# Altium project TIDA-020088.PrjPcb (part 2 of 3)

## Sheet TIDA-020088_TAS6684_1.SchDoc
size 431 x 279 mm; Date: Not shown in title block; ApprovedBy: Not shown in title block; CheckedBy: Not shown in title block; Author: Not shown in title block; CompanyName: Not shown in title block; Engineer: Not shown in title block; Organization: Not shown in title block; Address1: Not shown in title block; Address2: Not shown in title block; Address3: Not shown in title block; Address4: Not shown in title block; DocumentNumber: 1; Revision: Use project parameter SCH_Rev; SheetNumber: 7; SheetTotal: 8; PageSetup: Record=PageOptions¦CenterHorizontal=True¦CenterVertical=True¦PrintScale=1.00¦XCorrection=1.00¦YCorrection=1.00¦PrintKind=0¦BorderSize=5000000¦LeftOffset=0¦BottomOffset=0¦Orientation=2¦PaperLength=1000¦PaperWidth=1000¦Scale=100¦PaperSource=15¦PrintQuality=600¦MediaType=1¦DitherType=10¦PaperKind=Letter¦PrintScaleMode=1
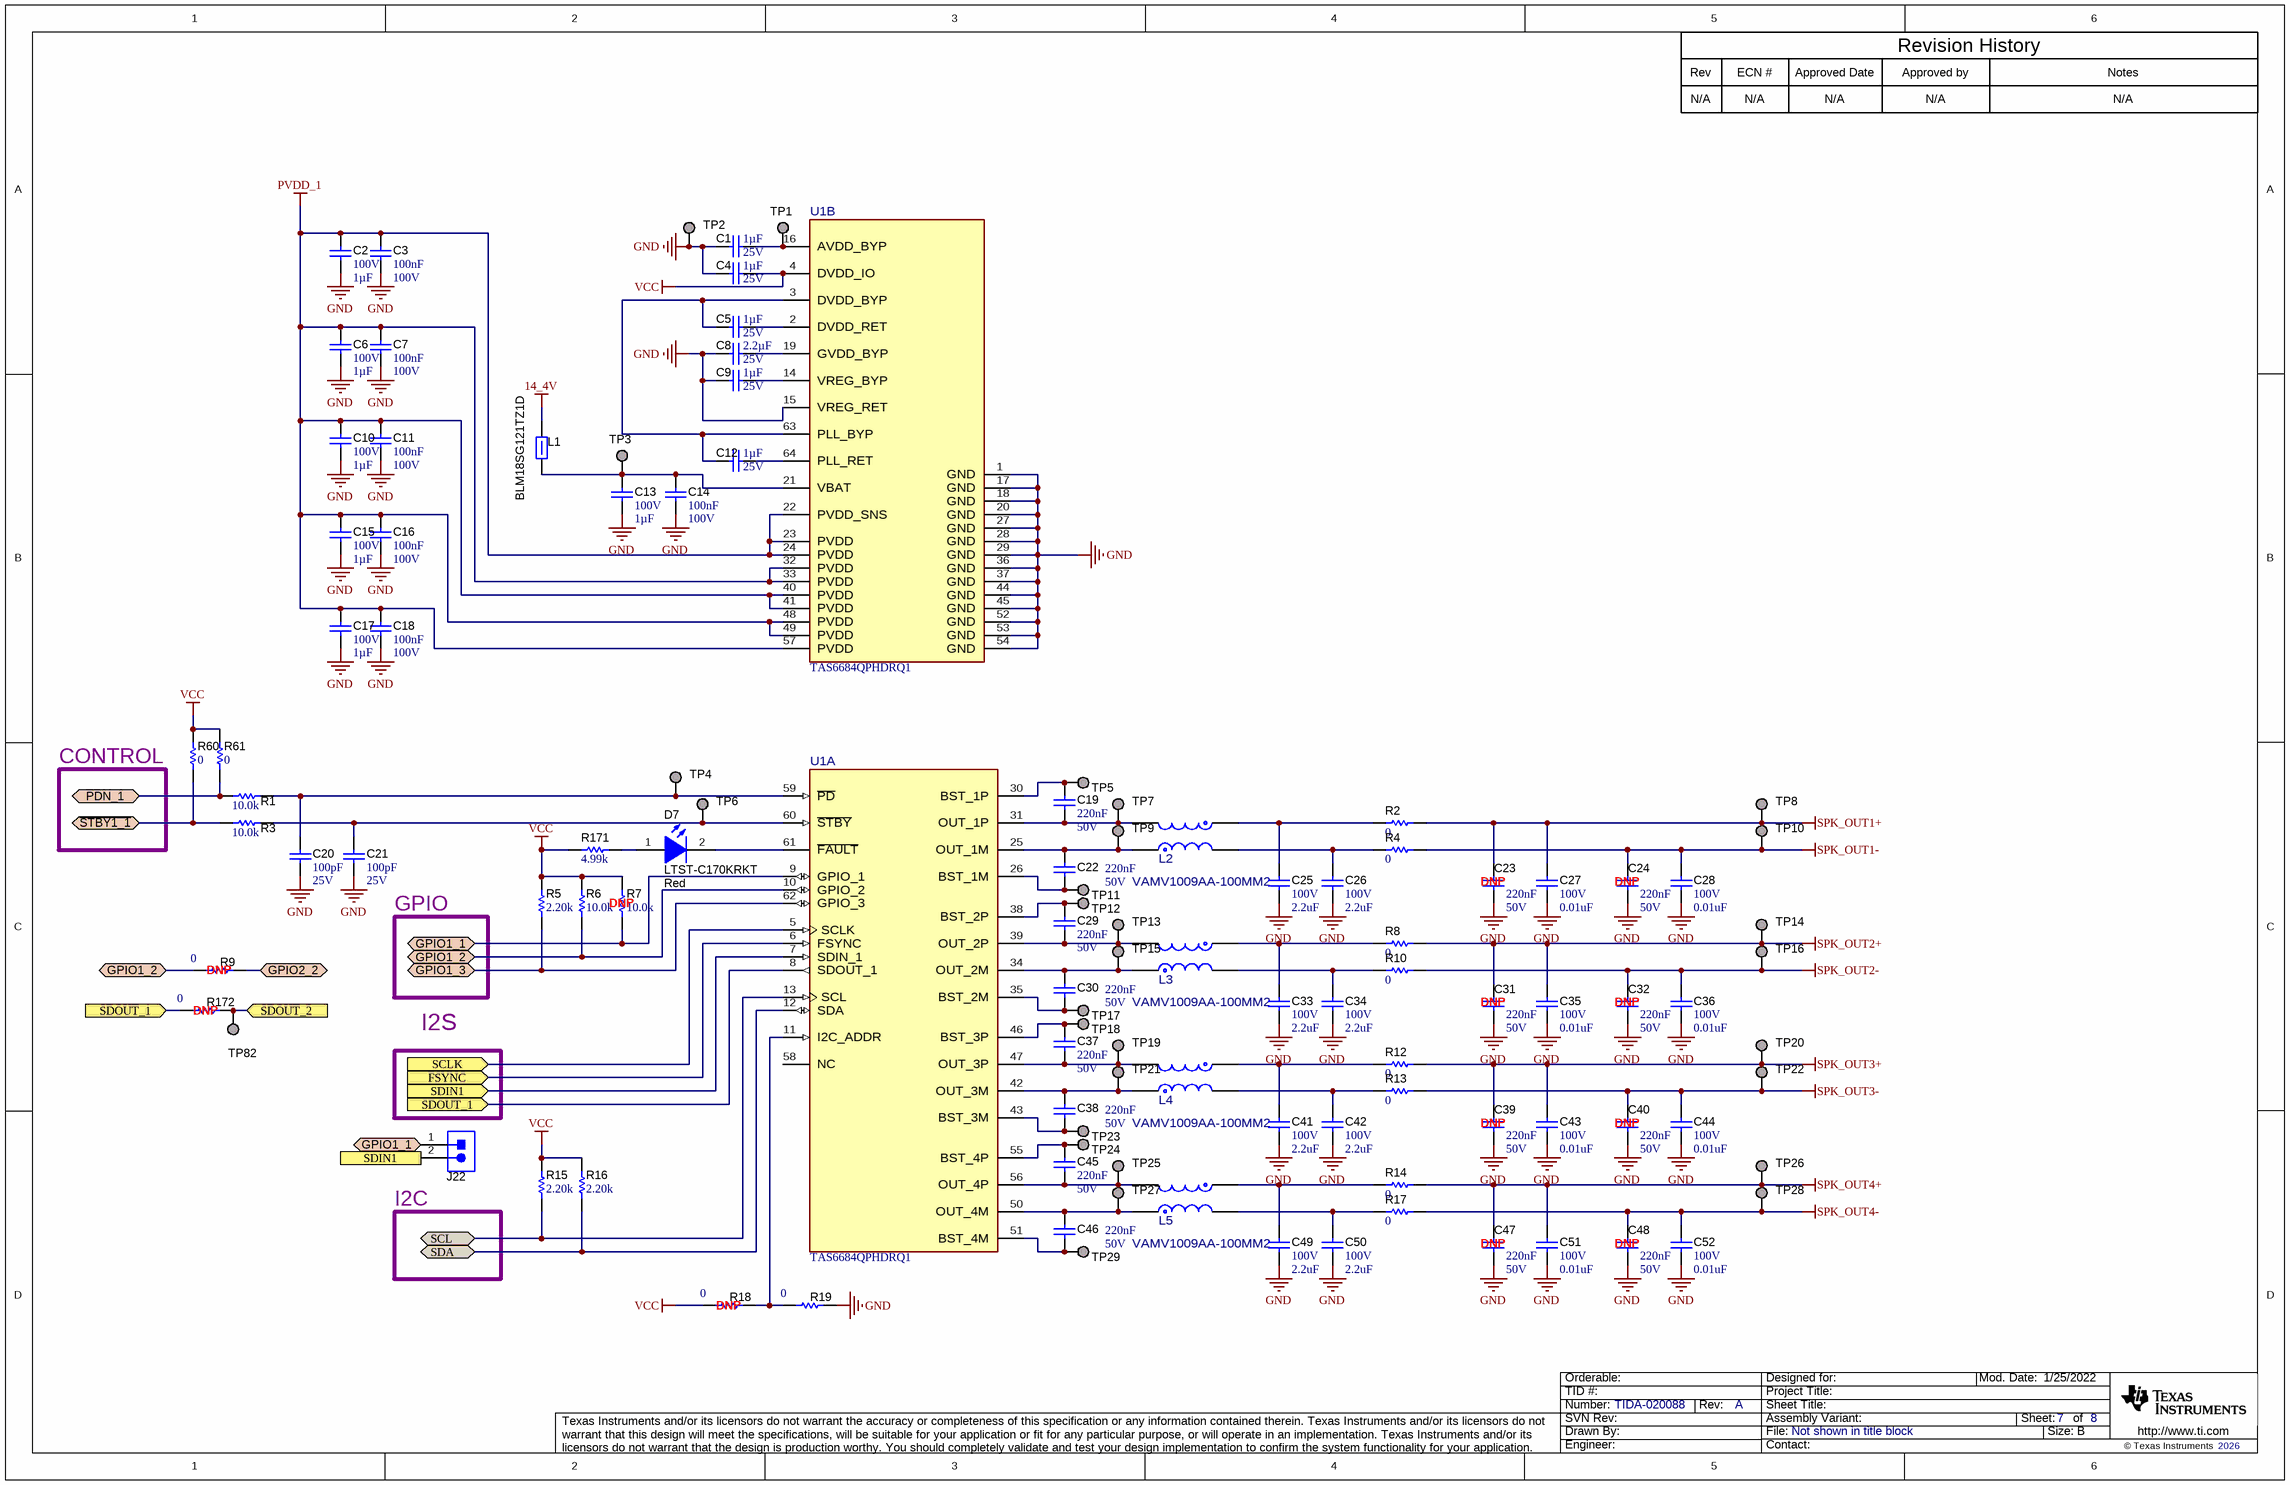
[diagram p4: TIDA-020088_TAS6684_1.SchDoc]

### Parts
C1  Cap_F: 1µF  VDC_V: 25V  [0603]  (hidden comment: GCM188R71E105KA64D)
C2  VDC_V: 100V  ValueDisplayed: 1µF  [1206]  (hidden comment: GCJ31CR72A105KA01K)
C3  Cap_F: 100nF  VDC_V: 100V  [0603]  (hidden comment: GCJ188R72A104KA01D)
C4  Cap_F: 1µF  VDC_V: 25V  [0603]  (hidden comment: GCM188R71E105KA64D)
C5  Cap_F: 1µF  VDC_V: 25V  [0603]  (hidden comment: GCM188R71E105KA64D)
C6  VDC_V: 100V  ValueDisplayed: 1µF  [1206]  (hidden comment: GCJ31CR72A105KA01K)
C7  Cap_F: 100nF  VDC_V: 100V  [0603]  (hidden comment: GCJ188R72A104KA01D)
C8  Cap_F: 2.2µF  VDC_V: 25V  [0805_HV]  (hidden comment: GCM21BR71E225KA73L)
C9  Cap_F: 1µF  VDC_V: 25V  [0603]  (hidden comment: GCM188R71E105KA64D)
C10  VDC_V: 100V  ValueDisplayed: 1µF  [1206]  (hidden comment: GCJ31CR72A105KA01K)
C11  Cap_F: 100nF  VDC_V: 100V  [0603]  (hidden comment: GCJ188R72A104KA01D)
C12  Cap_F: 1µF  VDC_V: 25V  [0603]  (hidden comment: GCM188R71E105KA64D)
C13  VDC_V: 100V  ValueDisplayed: 1µF  [1206]  (hidden comment: GCJ31CR72A105KA01K)
C14  Cap_F: 100nF  VDC_V: 100V  [0603]  (hidden comment: GCJ188R72A104KA01D)
C15  VDC_V: 100V  ValueDisplayed: 1µF  [1206]  (hidden comment: GCJ31CR72A105KA01K)
C16  Cap_F: 100nF  VDC_V: 100V  [0603]  (hidden comment: GCJ188R72A104KA01D)
C17  VDC_V: 100V  ValueDisplayed: 1µF  [1206]  (hidden comment: GCJ31CR72A105KA01K)
C18  Cap_F: 100nF  VDC_V: 100V  [0603]  (hidden comment: GCJ188R72A104KA01D)
C19  Cap_F: 220nF  VDC_V: 50V  [0603]  (hidden comment: GCM188R71H224KA64D)
C20  Cap_F: 100pF  VDC_V: 25V  [0201_033]  (hidden comment: GCM033R71E101KA03D)
C21  Cap_F: 100pF  VDC_V: 25V  [0201_033]  (hidden comment: GCM033R71E101KA03D)
C22  Cap_F: 220nF  VDC_V: 50V  [0603]  (hidden comment: GCM188R71H224KA64D)
C23  DNP  Cap_F: 220nF  VDC_V: 50V  [0603]  (no BOM)
C24  DNP  Cap_F: 220nF  VDC_V: 50V  [0603]  (no BOM)
C25  VDC_V: 100V  ValueDisplayed: 2.2uF  [1210_250]  (hidden comment: CGA6N3X7R2A225K230AB)
C26  VDC_V: 100V  ValueDisplayed: 2.2uF  [1210_250]  (hidden comment: CGA6N3X7R2A225K230AB)
C27  VDC_V: 100V  ValueDisplayed: 0.01uF  [0603]  (hidden comment: CGA3E2X7R2A103K080AA)
C28  VDC_V: 100V  ValueDisplayed: 0.01uF  [0603]  (hidden comment: CGA3E2X7R2A103K080AA)
C29  Cap_F: 220nF  VDC_V: 50V  [0603]  (hidden comment: GCM188R71H224KA64D)
C30  Cap_F: 220nF  VDC_V: 50V  [0603]  (hidden comment: GCM188R71H224KA64D)
C31  DNP  Cap_F: 220nF  VDC_V: 50V  [0603]  (no BOM)
C32  DNP  Cap_F: 220nF  VDC_V: 50V  [0603]  (no BOM)
C33  VDC_V: 100V  ValueDisplayed: 2.2uF  [1210_250]  (hidden comment: CGA6N3X7R2A225K230AB)
C34  VDC_V: 100V  ValueDisplayed: 2.2uF  [1210_250]  (hidden comment: CGA6N3X7R2A225K230AB)
C35  VDC_V: 100V  ValueDisplayed: 0.01uF  [0603]  (hidden comment: CGA3E2X7R2A103K080AA)
C36  VDC_V: 100V  ValueDisplayed: 0.01uF  [0603]  (hidden comment: CGA3E2X7R2A103K080AA)
C37  Cap_F: 220nF  VDC_V: 50V  [0603]  (hidden comment: GCM188R71H224KA64D)
C38  Cap_F: 220nF  VDC_V: 50V  [0603]  (hidden comment: GCM188R71H224KA64D)
C39  DNP  Cap_F: 220nF  VDC_V: 50V  [0603]  (no BOM)
C40  DNP  Cap_F: 220nF  VDC_V: 50V  [0603]  (no BOM)
C41  VDC_V: 100V  ValueDisplayed: 2.2uF  [1210_250]  (hidden comment: CGA6N3X7R2A225K230AB)
C42  VDC_V: 100V  ValueDisplayed: 2.2uF  [1210_250]  (hidden comment: CGA6N3X7R2A225K230AB)
C43  VDC_V: 100V  ValueDisplayed: 0.01uF  [0603]  (hidden comment: CGA3E2X7R2A103K080AA)
C44  VDC_V: 100V  ValueDisplayed: 0.01uF  [0603]  (hidden comment: CGA3E2X7R2A103K080AA)
C45  Cap_F: 220nF  VDC_V: 50V  [0603]  (hidden comment: GCM188R71H224KA64D)
C46  Cap_F: 220nF  VDC_V: 50V  [0603]  (hidden comment: GCM188R71H224KA64D)
C47  DNP  Cap_F: 220nF  VDC_V: 50V  [0603]  (no BOM)
C48  DNP  Cap_F: 220nF  VDC_V: 50V  [0603]  (no BOM)
C49  VDC_V: 100V  ValueDisplayed: 2.2uF  [1210_250]  (hidden comment: CGA6N3X7R2A225K230AB)
C50  VDC_V: 100V  ValueDisplayed: 2.2uF  [1210_250]  (hidden comment: CGA6N3X7R2A225K230AB)
C51  VDC_V: 100V  ValueDisplayed: 0.01uF  [0603]  (hidden comment: CGA3E2X7R2A103K080AA)
C52  VDC_V: 100V  ValueDisplayed: 0.01uF  [0603]  (hidden comment: CGA3E2X7R2A103K080AA)
D7  LTST-C170KRKT  value Red  [LED_LTST-C170_Red]
J22  TSW-102-07-G-S  [TSW-102-07-G-S]  (value not drawn)
L1  BLM18SG121TZ1D  [0603]
L2  VAMV1009AA-100MM2  [FP-VAMV1009AA-100MM2_SMT_CMC_9MM2_10MM2-MFG]
L3  VAMV1009AA-100MM2  [FP-VAMV1009AA-100MM2_SMT_CMC_9MM2_10MM2-MFG]
L4  VAMV1009AA-100MM2  [FP-VAMV1009AA-100MM2_SMT_CMC_9MM2_10MM2-MFG]
L5  VAMV1009AA-100MM2  [FP-VAMV1009AA-100MM2_SMT_CMC_9MM2_10MM2-MFG]
R1  ValueDisplayed: 10.0k  [0402]  (hidden comment: CRCW040210K0FKED)
R2  ValueDisplayed: 0  [1210]  (hidden comment: CRCW12100000Z0EAHP)
R3  ValueDisplayed: 10.0k  [0402]  (hidden comment: CRCW040210K0FKED)
R4  ValueDisplayed: 0  [1210]  (hidden comment: CRCW12100000Z0EAHP)
R5  ValueDisplayed: 2.20k  [0402]  (hidden comment: CRCW04022K20FKED)
R6  ValueDisplayed: 10.0k  [0402]  (hidden comment: CRCW040210K0FKED)
R7  DNP  ValueDisplayed: 10.0k  [0402]  (no BOM)
R8  ValueDisplayed: 0  [1210]  (hidden comment: CRCW12100000Z0EAHP)
R9  DNP  ValueDisplayed: 0  [0603]  (no BOM)
R10  ValueDisplayed: 0  [1210]  (hidden comment: CRCW12100000Z0EAHP)
R12  ValueDisplayed: 0  [1210]  (hidden comment: CRCW12100000Z0EAHP)
R13  ValueDisplayed: 0  [1210]  (hidden comment: CRCW12100000Z0EAHP)
R14  ValueDisplayed: 0  [1210]  (hidden comment: CRCW12100000Z0EAHP)
R15  ValueDisplayed: 2.20k  [0402]  (hidden comment: CRCW04022K20FKED)
R16  ValueDisplayed: 2.20k  [0402]  (hidden comment: CRCW04022K20FKED)
R17  ValueDisplayed: 0  [1210]  (hidden comment: CRCW12100000Z0EAHP)
R18  DNP  ValueDisplayed: 0  [0603]  (no BOM)
R19  ValueDisplayed: 0  [0603]  (hidden comment: CRCW06030000Z0EA)
R60  ValueDisplayed: 0  [0603]  (hidden comment: CRCW06030000Z0EA)
R61  ValueDisplayed: 0  [0603]  (hidden comment: CRCW06030000Z0EA)
R171  ValueDisplayed: 4.99k  [0402]  (hidden comment: CRCW04024K99FKED)
R172  DNP  ValueDisplayed: 0  [0603]  (no BOM)
TP1  TP_SM_1MM  [TP_SM_1MM]  (value not drawn)  (no BOM)
TP2  TP_SM_1MM  [TP_SM_1MM]  (value not drawn)  (no BOM)
TP3  TP_SM_1MM  [TP_SM_1MM]  (value not drawn)  (no BOM)
TP4  TP_SM_1MM  [TP_SM_1MM]  (value not drawn)  (no BOM)
TP5  TP_SM_1MM  [TP_SM_1MM]  (value not drawn)  (no BOM)
TP6  TP_SM_1MM  [TP_SM_1MM]  (value not drawn)  (no BOM)
TP7  TP_SM_1MM  [TP_SM_1MM]  (value not drawn)  (no BOM)
TP8  TP_SM_1MM  [TP_SM_1MM]  (value not drawn)  (no BOM)
TP9  TP_SM_1MM  [TP_SM_1MM]  (value not drawn)  (no BOM)
TP10  TP_SM_1MM  [TP_SM_1MM]  (value not drawn)  (no BOM)
TP11  TP_SM_1MM  [TP_SM_1MM]  (value not drawn)  (no BOM)
TP12  TP_SM_1MM  [TP_SM_1MM]  (value not drawn)  (no BOM)
TP13  TP_SM_1MM  [TP_SM_1MM]  (value not drawn)  (no BOM)
TP14  TP_SM_1MM  [TP_SM_1MM]  (value not drawn)  (no BOM)
TP15  TP_SM_1MM  [TP_SM_1MM]  (value not drawn)  (no BOM)
TP16  TP_SM_1MM  [TP_SM_1MM]  (value not drawn)  (no BOM)
TP17  TP_SM_1MM  [TP_SM_1MM]  (value not drawn)  (no BOM)
TP18  TP_SM_1MM  [TP_SM_1MM]  (value not drawn)  (no BOM)
TP19  TP_SM_1MM  [TP_SM_1MM]  (value not drawn)  (no BOM)
TP20  TP_SM_1MM  [TP_SM_1MM]  (value not drawn)  (no BOM)
TP21  TP_SM_1MM  [TP_SM_1MM]  (value not drawn)  (no BOM)
TP22  TP_SM_1MM  [TP_SM_1MM]  (value not drawn)  (no BOM)
TP23  TP_SM_1MM  [TP_SM_1MM]  (value not drawn)  (no BOM)
TP24  TP_SM_1MM  [TP_SM_1MM]  (value not drawn)  (no BOM)
TP25  TP_SM_1MM  [TP_SM_1MM]  (value not drawn)  (no BOM)
TP26  TP_SM_1MM  [TP_SM_1MM]  (value not drawn)  (no BOM)
TP27  TP_SM_1MM  [TP_SM_1MM]  (value not drawn)  (no BOM)
TP28  TP_SM_1MM  [TP_SM_1MM]  (value not drawn)  (no BOM)
TP29  TP_SM_1MM  [TP_SM_1MM]  (value not drawn)  (no BOM)
TP82  TP_SM_1MM  [TP_SM_1MM]  (value not drawn)  (no BOM)
U1  TAS6684QPHDRQ1  [PHD0064B-MFG]  (parts A,B of 2)

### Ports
FSYNC (in), GPIO1_1 (bidir), GPIO1_2 (bidir), GPIO1_3 (bidir), GPIO2_2 (bidir), PDN_1 (bidir), SCL (bidir), SCLK (in), SDA (bidir), SDIN1 (in), SDOUT_1 (in), SDOUT_2 (in), ~{STBY1_1} (bidir)

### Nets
14_4V: L1.1  [project net BIAS]
GND: C1.1 C2.2 C3.1 C4.1 C6.2 C7.2 C8.2 C9.1 C10.2 C11.2 C13.2 C14.2 C15.2 C16.2 C17.2 C18.2 C20.2 C21.2 C23.2 C24.2 C25.2 C26.2 C27.2 C28.2 C31.2 C32.2 C33.2 C34.2 C35.2 C36.2 C39.2 C40.2 C41.2 C42.2 C43.2 C44.2 C47.2 C48.2 C49.2 C50.2 C51.2 C52.2 R19.2 TP2.1 U1.1(GND) U1.15(VREG_RET) U1.17(GND) U1.18(GND) U1.20(GND) U1.27(GND) U1.28(GND) U1.29(GND) U1.36(GND) U1.37(GND) U1.44(GND) U1.45(GND) U1.52(GND) U1.53(GND) U1.54(GND)
PVDD_1: C2.1 C3.2 C6.1 C7.1 C10.1 C11.1 C15.1 C16.1 C17.1 C18.1 U1.22(PVDD_SNS) U1.23(PVDD) U1.24(PVDD) U1.32(PVDD) U1.33(PVDD) U1.40(PVDD) U1.41(PVDD) U1.48(PVDD) U1.49(PVDD) U1.57(PVDD)
SPK_OUT1+: C23.1 C27.1 R2.2 TP8.1
SPK_OUT1-: C24.1 C28.1 R4.2 TP10.1
SPK_OUT2+: C31.1 C35.1 R8.2 TP14.1
SPK_OUT2-: C32.1 C36.1 R10.2 TP16.1
SPK_OUT3+: C39.1 C43.1 R12.2 TP20.1
SPK_OUT3-: C40.1 C44.1 R13.2 TP22.1
SPK_OUT4+: C47.1 C51.1 R14.2 TP26.1
SPK_OUT4-: C48.1 C52.1 R17.2 TP28.1
VCC: C4.2 R5.2 R6.2 R7.2 R15.2 R16.2 R18.1 R60.2 R61.2 R171.1 U1.4(DVDD_IO)
NetC1_2: C1.2 TP1.1 U1.16(AVDD_BYP)
NetC5_1: C5.1 C12.1 U1.3(DVDD_BYP) U1.63(PLL_BYP)
NetC5_2: C5.2 U1.2(DVDD_RET)
NetC8_1: C8.1 U1.19(GVDD_BYP)
NetC9_2: C9.2 U1.14(VREG_BYP)
NetC12_2: C12.2 U1.64(PLL_RET)
NetC13_1: C13.1 C14.1 L1.2 TP3.1 U1.21(VBAT)
NetC19_1: C19.1 TP5.1 U1.30(BST_1P)
NetC19_2: C19.2 L2.4(2_Finish) TP7.1 U1.31(OUT_1P)
NetC20_1: C20.1 R1.1 TP4.1 U1.59(~{PD})
NetC21_1: C21.1 R3.2 TP6.1 U1.60(~{STBY})
NetC22_1: C22.1 L2.1(1_Start) TP9.1 U1.25(OUT_1M)
NetC22_2: C22.2 TP11.1 U1.26(BST_1M)
NetC25_1: C25.1 L2.3(2_Start) R2.1
NetC26_1: C26.1 L2.2(1_Finish) R4.1
NetC29_1: C29.1 TP12.1 U1.38(BST_2P)
NetC29_2: C29.2 L3.4(2_Finish) TP13.1 U1.39(OUT_2P)
NetC30_1: C30.1 L3.1(1_Start) TP15.1 U1.34(OUT_2M)
NetC30_2: C30.2 TP17.1 U1.35(BST_2M)
NetC33_1: C33.1 L3.3(2_Start) R8.1
NetC34_1: C34.1 L3.2(1_Finish) R10.1
NetC37_1: C37.1 TP18.1 U1.46(BST_3P)
NetC37_2: C37.2 L4.4(2_Finish) TP19.1 U1.47(OUT_3P)
NetC38_1: C38.1 L4.1(1_Start) TP21.1 U1.42(OUT_3M)
NetC38_2: C38.2 TP23.1 U1.43(BST_3M)
NetC41_1: C41.1 L4.3(2_Start) R12.1
NetC42_1: C42.1 L4.2(1_Finish) R13.1
NetC45_1: C45.1 TP24.1 U1.55(BST_4P)
NetC45_2: C45.2 L5.4(2_Finish) TP25.1 U1.56(OUT_4P)
NetC46_1: C46.1 L5.1(1_Start) TP27.1 U1.50(OUT_4M)
NetC46_2: C46.2 TP29.1 U1.51(BST_4M)
NetC49_1: C49.1 L5.3(2_Start) R14.1
NetC50_1: C50.1 L5.2(1_Finish) R17.1
NetD7_1: D7.1(A) R171.2
NetD7_2: D7.2(K) U1.61(~{FAULT})
NetJ2_2: U1.5(SCLK) ; port SCLK
NetJ4_2: U1.6(FSYNC) ; port FSYNC
NetJ6_2: J22.2 U1.7(SDIN_1) ; port SDIN1
NetJ11_2: R15.1 U1.13(SCL) ; port SCL
NetJ11_3: R16.1 U1.12(SDA) ; port SDA
NetJ22_1: J22.1 R7.1 U1.9(GPIO_1) ; port GPIO1_1
NetR1_2: R1.2 R61.1 ; port PDN_1
NetR3_1: R3.1 R60.1 ; port ~{STBY1_1}
NetR5_1: R5.1 U1.62(GPIO_3) ; port GPIO1_3
NetR6_1: R6.1 R9.1 U1.10(GPIO_2) ; port GPIO1_2
NetR9_2: R9.2 ; port GPIO2_2
NetR18_2: R18.2 R19.1 U1.11(I2C_ADDR)
NetR142_2: R172.1 U1.8(SDOUT_1) ; port SDOUT_1
NetR143_2: R172.2 TP82.1 ; port SDOUT_2

Not connected (* = marked no-connect by the designer): U1 58(NC)

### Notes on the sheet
- Rev
- N/A
- ECN #
- Approved Date
- Approved by
- Revision History
- Notes
- CONTROL
- (near C21) GPIO
- I2S
- (near J22) I2C

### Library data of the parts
C1 C4 C5 C9 C12 = CMP-0007139-3: CAP, CERM, 1 uF, 25 V, +/- 10%, X7R, AEC-Q200 Grade 1, 0603; Manufacturer: MuRata; TaMin_C: -55°C; Polarized: N; SizeAreaWB_mm2: 4.68; Value1: Unknown; U/M: EA; Value: 1uF; TaMax_C: 125°C; SizeZ_mm: 1; SizeX_mm: 1.6; SizeY_mm: 0.8; SizeArea_mm2: 1.28; AEC Qualified: Y; AEC Category: Q200
C2 C6 C10 C13 C15 C17 = CMP-0750040-1: CAP, CERM, 1 µF, 100 V,+/- 10%, X7R, AEC-Q200 Grade 1, 1206; Manufacturer: MuRata; Value: 1uF; U/M: EA; SizeX_mm: 3.2; Polarized: N; TaMin_C: -55°C; SizeZ_mm: 1.35; SizeY_mm: 1.6; AEC Category: Q200; SizeArea_mm2: 5.12; TaMax_C: 125°C; AEC Grade: 1; AEC Qualified: Y; SizeAreaWB_mm2: 10.92
C3 C7 C11 C14 C16 C18 = CMP-0064935-2: CAP, CERM, 0.1 uF, 100 V,+/- 10%, X7R, AEC-Q200 Grade 1, 0603; Manufacturer: MuRata; TaMin_C: -55°C; Polarized: N; SizeAreaWB_mm2: 4.68; Value1: Unknown; U/M: EA; Value: 0.1uF; TaMax_C: 125°C; SizeZ_mm: 1; SizeX_mm: 1.6; SizeY_mm: 0.8; SizeArea_mm2: 1.28; AEC Qualified: Y; AEC Category: Q200
C8 = CMP-0083622-1: CAP, CERM, 2.2 µF, 25 V,+/- 10%, X7R, AEC-Q200 Grade 1, 0805; Manufacturer: MuRata; TaMin_C: -55°C; Polarized: N; SizeAreaWB_mm2: 6.75; U/M: EA; Value: 2.2uF; TaMax_C: 125°C; SizeZ_mm: 1.45; SizeX_mm: 2; SizeY_mm: 1.25; Cap_Case: 0805; SizeArea_mm2: 2.5; AEC Qualified: Y; AEC Grade: 1; AEC Category: Q200
C19 C22 C29 C30 C37 C38 C45 C46 = CMP-0007145-4: CAP, CERM, 0.22 uF, 50 V, +/- 10%, X7R, AEC-Q200 Grade 1, 0603; Manufacturer: MuRata; TaMin_C: -55°C; Polarized: N; SizeAreaWB_mm2: 4.68; Value1: Unknown; U/M: EA; Value: 0.22uF; TaMax_C: 125°C; SizeZ_mm: 1; SizeX_mm: 1.6; SizeY_mm: 0.8; SizeArea_mm2: 1.28; AEC Qualified: Y; AEC Category: Q200
C20 C21 = CMP-0009660-3: CAP, CERM, 100 pF, 25 V, +/- 10%, X7R, AEC-Q200 Grade 1, 0201; Manufacturer: MuRata; TaMin_C: -55°C; Polarized: N; SizeAreaWB_mm2: 2.08; U/M: EA; Value: 100pF; TaMax_C: 125°C; SizeZ_mm: 0.33; SizeX_mm: 0.6; SizeY_mm: 0.3; Cap_Case: 0201; SizeArea_mm2: 0.18; AEC Qualified: Y; AEC Grade: 1; AEC Category: Q200; Value1: Unknown
C23 C24 C31 C32 C39 C40 C47 C48 = CMP-0007145-4: CAP, CERM, 0.22 uF, 50 V, +/- 10%, X7R, AEC-Q200 Grade 1, 0603; Manufacturer: MuRata; PartNumber: GCM188R71H224KA64D; TaMin_C: -55°C; Polarized: N; SizeAreaWB_mm2: 4.68; Value1: Unknown; U/M: EA; Value: 0.22uF; TaMax_C: 125°C; SizeZ_mm: 1; SizeX_mm: 1.6; SizeY_mm: 0.8; SizeArea_mm2: 1.28; AEC Qualified: Y; AEC Category: Q200
C25 C26 C33 C34 C41 C42 C49 C50 = CMP-0009152-2: CAP, CERM, 2.2 uF, 100 V, +/- 10%, X7R, AEC-Q200 Grade 1,; Manufacturer: TDK; TaMin_C: -55°C; ESR_ohm: 1.73m; Polarized: N; SizeAreaWB_mm2: 14.7; Value1: 0.00173 ohm; U/M: EA; Value: 2.2uF; TaMax_C: 125°C; SizeZ_mm: 2.5; SizeX_mm: 3.2; SizeArea_mm2: 8; AEC Qualified: Y; Cap_F: 2.2µF; IRMS_A: 5.5932A; AEC Grade: 1; AEC Category: Q200
C27 C28 C35 C36 C43 C44 C51 C52 = CMP-0007082-4: CAP, CERM, 0.01 uF, 100 V, +/- 10%, X7R, AEC-Q200 Grade 1, 0603; Manufacturer: TDK; Value: 0.01uF; SizeZ_mm: 1; AEC Qualified: Y; Cap_F: 10nF; TaMin_C: -55°C; ESR_ohm: 0.2354; Polarized: N; SizeAreaWB_mm2: 4.68; Value1: 0.235428 ohm; U/M: EA; TaMax_C: 125°C; SizeX_mm: 1.6; SizeY_mm: 0.8; SizeArea_mm2: 1.28; IRMS_A: 396.995mA; AEC Category: Q200
D7 = CMP-0002829-3: LED, Red, SMD; Manufacturer: Lite-On; SizeZ_mm: 1.2; Value1: W; SizeY_mm: 1.25; Value2: 2V; SizeArea_mm2: 2.5; SizeX_mm: 2; SizeAreaWB_mm2: 6.75; Io_A: 20mA; Type: AlInGaP
J22 = CMP-0075405-2: Header, 100mil, 2x1, Gold, TH; Manufacturer: Samtec; Pitch_mm: 2.54; Cert_VDE: N; Gender: Male; Cert_CSA: Y; Voltage_V: 550V; Green_REACh: Passed; Current_A: 6.3A; Green_Lifecycle: Active; Row_Count: 1
L1 = CMP-0084877-1: Inductor, Ferrite Bead, Ferrite, 3 A, 120 ohm, AEC-Q200 Grade 1, SMD; Manufacturer: MuRata; SizeAreaWB_mm2: 4.68; DCR_ohm: 120; Value1: 120 ohm; Imax_A: 3A; SizeZ_mm: 1; SizeX_mm: 1.6; SizeY_mm: 0.8; SizeArea_mm2: 1.28; AEC Qualified: Y; AEC Category: Q200
L2-L5 = CMP-0093075-1: Power Choke Coil, 10uH 20% 100kHz, 22mΩ DCR max, Idc 5.8A, Isat 10A; Manufacturer: Cyntec; SizeZ_mm: 11.05mm; AEC Grade: Grade 1; DCR_ohm: 22m; Ind_H: 10µH; AEC Qualified: Yes; Material: Metal Dust
R1 R3 R6 = CMP-0025958-3: RES, 10.0 k, 1%, 0.063 W, AEC-Q200 Grade 0, 0402; Manufacturer: Vishay-Dale; Power_W: 63mW; TempCo: 100 ppm/C; Value_Code: 10k0; Value: 10.0k; EIA_Code: E96; Res_ohm: 10k; SizeX_mm: 1; SizeY_mm: 0.5; SizeZ_mm: 0.6; Value2: 0.063W; AEC Qualified: Y; VDC_V: 50V; AEC Category: Q200; AEC Grade: 0
R2 R4 R8 R10 R12-R14 R17 = CMP-0015017-3: RES, 0, 1%, 0.75 W, AEC-Q200 Grade 0, 1210; Manufacturer: Vishay-Dale; Power_W: 750mW; TempCo: ppm/C; SizeAreaWB_mm2: 14.7; Value: 0; SizeX_mm: 3.2; SizeY_mm: 2.5; SizeZ_mm: 1.35; Value2: 0.75W; SizeArea_mm2: 8; AEC Qualified: Y; AEC Category: Q200
R5 R15 R16 = CMP-0026231-2: RES, 2.20 k, 1%, 0.063 W, AEC-Q200 Grade 0, 0402; Manufacturer: Vishay-Dale; Power_W: 63mW; TempCo: 100 ppm/C; Value_Code: 2k20; Value: 2.20k; Res_ohm: 2.2k; SizeX_mm: 1; SizeY_mm: 0.5; SizeZ_mm: 0.6; Value2: 0.063W; AEC Qualified: Y; AEC Category: Q200; AEC Grade: 0
R7 = CMP-0025958-3: RES, 10.0 k, 1%, 0.063 W, AEC-Q200 Grade 0, 0402; Manufacturer: Vishay-Dale; PartNumber: CRCW040210K0FKED; Power_W: 63mW; TempCo: 100 ppm/C; Value_Code: 10k0; Value: 10.0k; EIA_Code: E96; Res_ohm: 10k; SizeX_mm: 1; SizeY_mm: 0.5; SizeZ_mm: 0.6; Value2: 0.063W; AEC Qualified: Y; VDC_V: 50V; AEC Category: Q200; AEC Grade: 0
R9 R18 R172 = CMP-0025697-4: RES, 0, 5%, 0.1 W, AEC-Q200 Grade 0, 0603; Manufacturer: Vishay-Dale; PartNumber: CRCW06030000Z0EA; AEC Qualified: Y; Power_W: 100mW; SizeZ_mm: 1; VDC_V: 75V; Value: 0; TempCo: 200 ppm/C; Value_Code: 0000; EIA_Code: E24; SizeX_mm: 1.6; SizeY_mm: 0.8; Value2: 0.1W; SizeArea_mm2: 1.28; AEC Category: Q200
R19 = CMP-0025697-4: RES, 0, 5%, 0.1 W, AEC-Q200 Grade 0, 0603; Manufacturer: Vishay-Dale; AEC Qualified: Y; Power_W: 100mW; SizeZ_mm: 1; VDC_V: 75V; Value: 0; TempCo: 200 ppm/C; Value_Code: 0000; EIA_Code: E24; SizeX_mm: 1.6; SizeY_mm: 0.8; Value2: 0.1W; SizeArea_mm2: 1.28; AEC Category: Q200
R60 R61 = CMP-0025697-4: RES, 0, 5%, 0.1 W, AEC-Q200 Grade 0, 0603; Manufacturer: Vishay-Dale; Power_W: 100mW; TempCo: 200 ppm/C; Value_Code: 0000; Value: 0; EIA_Code: E24; SizeX_mm: 1.6; SizeY_mm: 0.8; SizeZ_mm: 1; Value2: 0.1W; SizeArea_mm2: 1.28; AEC Qualified: Y; VDC_V: 75V; AEC Category: Q200
R171 = CMP-0026414-2: RES, 4.99 k, 1%, 0.063 W, AEC-Q200 Grade 0, 0402; Manufacturer: Vishay-Dale; Power_W: 63mW; TempCo: 100 ppm/C; Value_Code: 4k99; Value: 4.99k; EIA_Code: E96; SizeX_mm: 1; SizeY_mm: 0.5; SizeZ_mm: 0.6; Value2: 0.063W; AEC Qualified: Y; VDC_V: 50V; AEC Category: Q200; AEC Grade: 0
TP1-TP29 TP82 = CMP-0003825-1: 1mm Test Point, SMT; Manufacturer: Any
U1 = CMP-0122557-1: 45-V, 13-A Digital Input 4-Channel Automotive Class-D Audio Amplifier with Current Sense and Real-time Load Diagnostics; Manufacturer: Texas Instruments; SizeZ_mm: 1.2mm; AEC Qualified: Yes; AEC Grade: Grade 1; Max Supply Voltage: 45V; Min Supply Voltage: 4.5V; Number Of Channels: 4; Output Current Per Channel: 13A; Power At Speaker R: 215W @ 4Ω; Standoff Height: 0.05mm; TaMax_C: +125°C; TaMin_C: -40°C; TJmax_C: +175°C

## Sheet TIDA-020088_TAS6684_2.SchDoc
size 431 x 279 mm; Date: Not shown in title block; ApprovedBy: Not shown in title block; CheckedBy: Not shown in title block; Author: Not shown in title block; CompanyName: Not shown in title block; Engineer: Not shown in title block; Organization: Not shown in title block; Address1: Not shown in title block; Address2: Not shown in title block; Address3: Not shown in title block; Address4: Not shown in title block; DocumentNumber: 2; Revision: Use project parameter SCH_Rev; SheetNumber: 3; SheetTotal: 8; PageSetup: Record=PageOptions¦CenterHorizontal=True¦CenterVertical=True¦PrintScale=1.00¦XCorrection=1.00¦YCorrection=1.00¦PrintKind=0¦BorderSize=5000000¦LeftOffset=0¦BottomOffset=0¦Orientation=2¦PaperLength=1000¦PaperWidth=1000¦Scale=100¦PaperSource=15¦PrintQuality=600¦MediaType=1¦DitherType=10¦PaperKind=Letter¦PrintScaleMode=1
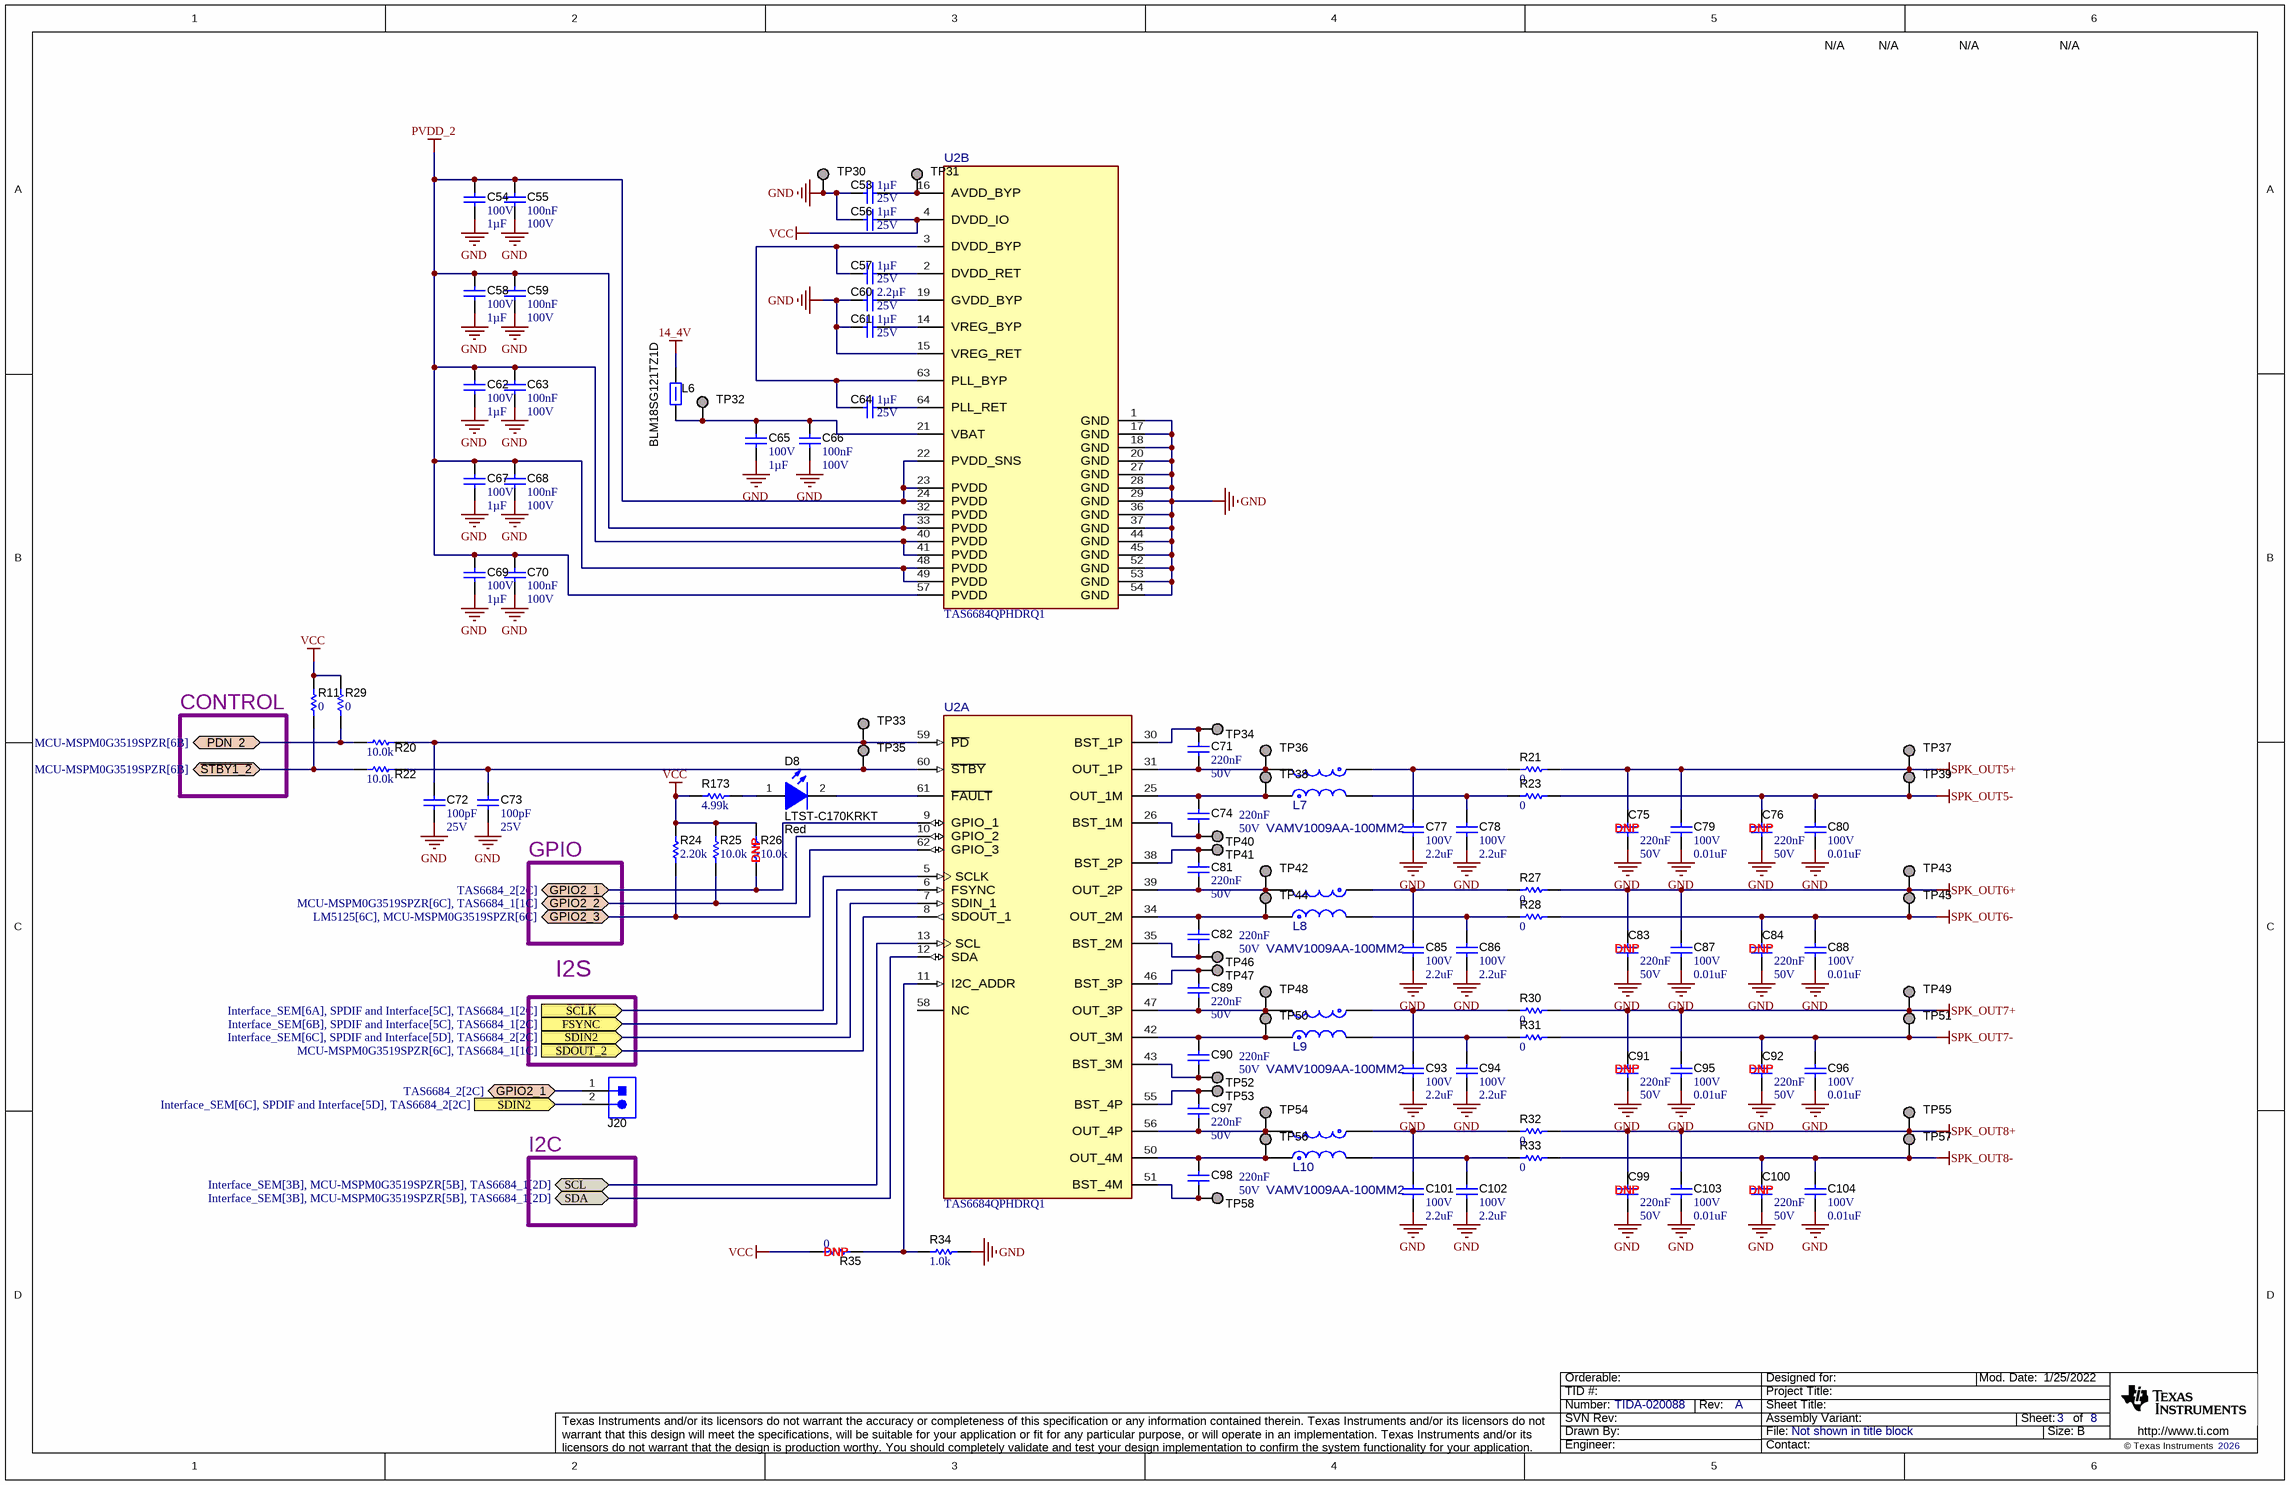
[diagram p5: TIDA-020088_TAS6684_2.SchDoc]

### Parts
C53  Cap_F: 1µF  VDC_V: 25V  [0603]  (hidden comment: GCM188R71E105KA64D)
C54  VDC_V: 100V  ValueDisplayed: 1µF  [1206]  (hidden comment: GCJ31CR72A105KA01K)
C55  Cap_F: 100nF  VDC_V: 100V  [0603]  (hidden comment: GCJ188R72A104KA01D)
C56  Cap_F: 1µF  VDC_V: 25V  [0603]  (hidden comment: GCM188R71E105KA64D)
C57  Cap_F: 1µF  VDC_V: 25V  [0603]  (hidden comment: GCM188R71E105KA64D)
C58  VDC_V: 100V  ValueDisplayed: 1µF  [1206]  (hidden comment: GCJ31CR72A105KA01K)
C59  Cap_F: 100nF  VDC_V: 100V  [0603]  (hidden comment: GCJ188R72A104KA01D)
C60  Cap_F: 2.2µF  VDC_V: 25V  [0805_HV]  (hidden comment: GCM21BR71E225KA73L)
C61  Cap_F: 1µF  VDC_V: 25V  [0603]  (hidden comment: GCM188R71E105KA64D)
C62  VDC_V: 100V  ValueDisplayed: 1µF  [1206]  (hidden comment: GCJ31CR72A105KA01K)
C63  Cap_F: 100nF  VDC_V: 100V  [0603]  (hidden comment: GCJ188R72A104KA01D)
C64  Cap_F: 1µF  VDC_V: 25V  [0603]  (hidden comment: GCM188R71E105KA64D)
C65  VDC_V: 100V  ValueDisplayed: 1µF  [1206]  (hidden comment: GCJ31CR72A105KA01K)
C66  Cap_F: 100nF  VDC_V: 100V  [0603]  (hidden comment: GCJ188R72A104KA01D)
C67  VDC_V: 100V  ValueDisplayed: 1µF  [1206]  (hidden comment: GCJ31CR72A105KA01K)
C68  Cap_F: 100nF  VDC_V: 100V  [0603]  (hidden comment: GCJ188R72A104KA01D)
C69  VDC_V: 100V  ValueDisplayed: 1µF  [1206]  (hidden comment: GCJ31CR72A105KA01K)
C70  Cap_F: 100nF  VDC_V: 100V  [0603]  (hidden comment: GCJ188R72A104KA01D)
C71  Cap_F: 220nF  VDC_V: 50V  [0603]  (hidden comment: GCM188R71H224KA64D)
C72  Cap_F: 100pF  VDC_V: 25V  [0201_033]  (hidden comment: GCM033R71E101KA03D)
C73  Cap_F: 100pF  VDC_V: 25V  [0201_033]  (hidden comment: GCM033R71E101KA03D)
C74  Cap_F: 220nF  VDC_V: 50V  [0603]  (hidden comment: GCM188R71H224KA64D)
C75  DNP  Cap_F: 220nF  VDC_V: 50V  [0603]  (no BOM)
C76  DNP  Cap_F: 220nF  VDC_V: 50V  [0603]  (no BOM)
C77  VDC_V: 100V  ValueDisplayed: 2.2uF  [1210_250]  (hidden comment: CGA6N3X7R2A225K230AB)
C78  VDC_V: 100V  ValueDisplayed: 2.2uF  [1210_250]  (hidden comment: CGA6N3X7R2A225K230AB)
C79  VDC_V: 100V  ValueDisplayed: 0.01uF  [0603]  (hidden comment: CGA3E2X7R2A103K080AA)
C80  VDC_V: 100V  ValueDisplayed: 0.01uF  [0603]  (hidden comment: CGA3E2X7R2A103K080AA)
C81  Cap_F: 220nF  VDC_V: 50V  [0603]  (hidden comment: GCM188R71H224KA64D)
C82  Cap_F: 220nF  VDC_V: 50V  [0603]  (hidden comment: GCM188R71H224KA64D)
C83  DNP  Cap_F: 220nF  VDC_V: 50V  [0603]  (no BOM)
C84  DNP  Cap_F: 220nF  VDC_V: 50V  [0603]  (no BOM)
C85  VDC_V: 100V  ValueDisplayed: 2.2uF  [1210_250]  (hidden comment: CGA6N3X7R2A225K230AB)
C86  VDC_V: 100V  ValueDisplayed: 2.2uF  [1210_250]  (hidden comment: CGA6N3X7R2A225K230AB)
C87  VDC_V: 100V  ValueDisplayed: 0.01uF  [0603]  (hidden comment: CGA3E2X7R2A103K080AA)
C88  VDC_V: 100V  ValueDisplayed: 0.01uF  [0603]  (hidden comment: CGA3E2X7R2A103K080AA)
C89  Cap_F: 220nF  VDC_V: 50V  [0603]  (hidden comment: GCM188R71H224KA64D)
C90  Cap_F: 220nF  VDC_V: 50V  [0603]  (hidden comment: GCM188R71H224KA64D)
C91  DNP  Cap_F: 220nF  VDC_V: 50V  [0603]  (no BOM)
C92  DNP  Cap_F: 220nF  VDC_V: 50V  [0603]  (no BOM)
C93  VDC_V: 100V  ValueDisplayed: 2.2uF  [1210_250]  (hidden comment: CGA6N3X7R2A225K230AB)
C94  VDC_V: 100V  ValueDisplayed: 2.2uF  [1210_250]  (hidden comment: CGA6N3X7R2A225K230AB)
C95  VDC_V: 100V  ValueDisplayed: 0.01uF  [0603]  (hidden comment: CGA3E2X7R2A103K080AA)
C96  VDC_V: 100V  ValueDisplayed: 0.01uF  [0603]  (hidden comment: CGA3E2X7R2A103K080AA)
C97  Cap_F: 220nF  VDC_V: 50V  [0603]  (hidden comment: GCM188R71H224KA64D)
C98  Cap_F: 220nF  VDC_V: 50V  [0603]  (hidden comment: GCM188R71H224KA64D)
C99  DNP  Cap_F: 220nF  VDC_V: 50V  [0603]  (no BOM)
C100  DNP  Cap_F: 220nF  VDC_V: 50V  [0603]  (no BOM)
C101  VDC_V: 100V  ValueDisplayed: 2.2uF  [1210_250]  (hidden comment: CGA6N3X7R2A225K230AB)
C102  VDC_V: 100V  ValueDisplayed: 2.2uF  [1210_250]  (hidden comment: CGA6N3X7R2A225K230AB)
C103  VDC_V: 100V  ValueDisplayed: 0.01uF  [0603]  (hidden comment: CGA3E2X7R2A103K080AA)
C104  VDC_V: 100V  ValueDisplayed: 0.01uF  [0603]  (hidden comment: CGA3E2X7R2A103K080AA)
D8  LTST-C170KRKT  value Red  [LED_LTST-C170_Red]
J20  TSW-102-07-G-S  [TSW-102-07-G-S]  (value not drawn)
L6  BLM18SG121TZ1D  [0603]
L7  VAMV1009AA-100MM2  [FP-VAMV1009AA-100MM2_SMT_CMC_9MM2_10MM2-MFG]
L8  VAMV1009AA-100MM2  [FP-VAMV1009AA-100MM2_SMT_CMC_9MM2_10MM2-MFG]
L9  VAMV1009AA-100MM2  [FP-VAMV1009AA-100MM2_SMT_CMC_9MM2_10MM2-MFG]
L10  VAMV1009AA-100MM2  [FP-VAMV1009AA-100MM2_SMT_CMC_9MM2_10MM2-MFG]
R11  ValueDisplayed: 0  [0603]  (hidden comment: CRCW06030000Z0EA)
R20  ValueDisplayed: 10.0k  [0402]  (hidden comment: CRCW040210K0FKED)
R21  ValueDisplayed: 0  [1210]  (hidden comment: CRCW12100000Z0EAHP)
R22  ValueDisplayed: 10.0k  [0402]  (hidden comment: CRCW040210K0FKED)
R23  ValueDisplayed: 0  [1210]  (hidden comment: CRCW12100000Z0EAHP)
R24  ValueDisplayed: 2.20k  [0402]  (hidden comment: CRCW04022K20FKED)
R25  ValueDisplayed: 10.0k  [0402]  (hidden comment: CRCW040210K0FKED)
R26  DNP  ValueDisplayed: 10.0k  [0402]  (no BOM)
R27  ValueDisplayed: 0  [1210]  (hidden comment: CRCW12100000Z0EAHP)
R28  ValueDisplayed: 0  [1210]  (hidden comment: CRCW12100000Z0EAHP)
R29  ValueDisplayed: 0  [0603]  (hidden comment: CRCW06030000Z0EA)
R30  ValueDisplayed: 0  [1210]  (hidden comment: CRCW12100000Z0EAHP)
R31  ValueDisplayed: 0  [1210]  (hidden comment: CRCW12100000Z0EAHP)
R32  ValueDisplayed: 0  [1210]  (hidden comment: CRCW12100000Z0EAHP)
R33  ValueDisplayed: 0  [1210]  (hidden comment: CRCW12100000Z0EAHP)
R34  ValueDisplayed: 1.0k  [0402]  (hidden comment: CRCW04021K00JNED)
R35  DNP  ValueDisplayed: 0  [0603]  (no BOM)
R173  ValueDisplayed: 4.99k  [0402]  (hidden comment: CRCW04024K99FKED)
TP30  TP_SM_1MM  [TP_SM_1MM]  (value not drawn)  (no BOM)
TP31  TP_SM_1MM  [TP_SM_1MM]  (value not drawn)  (no BOM)
TP32  TP_SM_1MM  [TP_SM_1MM]  (value not drawn)  (no BOM)
TP33  TP_SM_1MM  [TP_SM_1MM]  (value not drawn)  (no BOM)
TP34  TP_SM_1MM  [TP_SM_1MM]  (value not drawn)  (no BOM)
TP35  TP_SM_1MM  [TP_SM_1MM]  (value not drawn)  (no BOM)
TP36  TP_SM_1MM  [TP_SM_1MM]  (value not drawn)  (no BOM)
TP37  TP_SM_1MM  [TP_SM_1MM]  (value not drawn)  (no BOM)
TP38  TP_SM_1MM  [TP_SM_1MM]  (value not drawn)  (no BOM)
TP39  TP_SM_1MM  [TP_SM_1MM]  (value not drawn)  (no BOM)
TP40  TP_SM_1MM  [TP_SM_1MM]  (value not drawn)  (no BOM)
TP41  TP_SM_1MM  [TP_SM_1MM]  (value not drawn)  (no BOM)
TP42  TP_SM_1MM  [TP_SM_1MM]  (value not drawn)  (no BOM)
TP43  TP_SM_1MM  [TP_SM_1MM]  (value not drawn)  (no BOM)
TP44  TP_SM_1MM  [TP_SM_1MM]  (value not drawn)  (no BOM)
TP45  TP_SM_1MM  [TP_SM_1MM]  (value not drawn)  (no BOM)
TP46  TP_SM_1MM  [TP_SM_1MM]  (value not drawn)  (no BOM)
TP47  TP_SM_1MM  [TP_SM_1MM]  (value not drawn)  (no BOM)
TP48  TP_SM_1MM  [TP_SM_1MM]  (value not drawn)  (no BOM)
TP49  TP_SM_1MM  [TP_SM_1MM]  (value not drawn)  (no BOM)
TP50  TP_SM_1MM  [TP_SM_1MM]  (value not drawn)  (no BOM)
TP51  TP_SM_1MM  [TP_SM_1MM]  (value not drawn)  (no BOM)
TP52  TP_SM_1MM  [TP_SM_1MM]  (value not drawn)  (no BOM)
TP53  TP_SM_1MM  [TP_SM_1MM]  (value not drawn)  (no BOM)
TP54  TP_SM_1MM  [TP_SM_1MM]  (value not drawn)  (no BOM)
TP55  TP_SM_1MM  [TP_SM_1MM]  (value not drawn)  (no BOM)
TP56  TP_SM_1MM  [TP_SM_1MM]  (value not drawn)  (no BOM)
TP57  TP_SM_1MM  [TP_SM_1MM]  (value not drawn)  (no BOM)
TP58  TP_SM_1MM  [TP_SM_1MM]  (value not drawn)  (no BOM)
U2  TAS6684QPHDRQ1  [PHD0064B-MFG]  (parts A,B of 2)

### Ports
FSYNC (in, see Interface_SEM[6B], SPDIF and Interface[5C], TAS6684_1[2C]), GPIO2_1 (bidir, see TAS6684_2[2C]), GPIO2_2 (bidir, see MCU-MSPM0G3519SPZR[6C], TAS6684_1[1C]), GPIO2_3 (bidir, see LM5125[6C], MCU-MSPM0G3519SPZR[6C]), PDN_2 (bidir, see MCU-MSPM0G3519SPZR[6B]), SCL (bidir, see Interface_SEM[3B], MCU-MSPM0G3519SPZR[5B], TAS6684_1[2D]), SCLK (in, see Interface_SEM[6A], SPDIF and Interface[5C], TAS6684_1[2C]), SDA (bidir, see Interface_SEM[3B], MCU-MSPM0G3519SPZR[5B], TAS6684_1[2D]), SDIN2 (in, see Interface_SEM[6C], SPDIF and Interface[5D], TAS6684_2[2C]), SDOUT_2 (in, see MCU-MSPM0G3519SPZR[6C], TAS6684_1[1C]), ~{STBY1_2} (bidir, see MCU-MSPM0G3519SPZR[6B])

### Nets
14_4V: L6.1  [project net BIAS]
GND: C53.1 C54.2 C55.1 C56.1 C58.2 C59.2 C60.2 C61.1 C62.2 C63.2 C65.2 C66.2 C67.2 C68.2 C69.2 C70.2 C72.2 C73.2 C75.2 C76.2 C77.2 C78.2 C79.2 C80.2 C83.2 C84.2 C85.2 C86.2 C87.2 C88.2 C91.2 C92.2 C93.2 C94.2 C95.2 C96.2 C99.2 C100.2 C101.2 C102.2 C103.2 C104.2 R34.2 TP30.1 U2.1(GND) U2.15(VREG_RET) U2.17(GND) U2.18(GND) U2.20(GND) U2.27(GND) U2.28(GND) U2.29(GND) U2.36(GND) U2.37(GND) U2.44(GND) U2.45(GND) U2.52(GND) U2.53(GND) U2.54(GND)
PVDD_2: C54.1 C55.2 C58.1 C59.1 C62.1 C63.1 C67.1 C68.1 C69.1 C70.1 U2.22(PVDD_SNS) U2.23(PVDD) U2.24(PVDD) U2.32(PVDD) U2.33(PVDD) U2.40(PVDD) U2.41(PVDD) U2.48(PVDD) U2.49(PVDD) U2.57(PVDD)
SPK_OUT5+: C75.1 C79.1 R21.2 TP37.1
SPK_OUT5-: C76.1 C80.1 R23.2 TP39.1
SPK_OUT6+: C83.1 C87.1 R27.2 TP43.1
SPK_OUT6-: C84.1 C88.1 R28.2 TP45.1
SPK_OUT7+: C91.1 C95.1 R30.2 TP49.1
SPK_OUT7-: C92.1 C96.1 R31.2 TP51.1
SPK_OUT8+: C99.1 C103.1 R32.2 TP55.1
SPK_OUT8-: C100.1 C104.1 R33.2 TP57.1
VCC: C56.2 R11.2 R24.2 R25.2 R26.2 R29.2 R35.1 R173.1 U2.4(DVDD_IO)
NetC53_2: C53.2 TP31.1 U2.16(AVDD_BYP)
NetC57_1: C57.1 C64.1 U2.3(DVDD_BYP) U2.63(PLL_BYP)
NetC57_2: C57.2 U2.2(DVDD_RET)
NetC60_1: C60.1 U2.19(GVDD_BYP)
NetC61_2: C61.2 U2.14(VREG_BYP)
NetC64_2: C64.2 U2.64(PLL_RET)
NetC65_1: C65.1 C66.1 L6.2 TP32.1 U2.21(VBAT)
NetC71_1: C71.1 TP34.1 U2.30(BST_1P)
NetC71_2: C71.2 L7.4(2_Finish) TP36.1 U2.31(OUT_1P)
NetC72_1: C72.1 R20.1 TP33.1 U2.59(~{PD})
NetC73_1: C73.1 R22.2 TP35.1 U2.60(~{STBY})
NetC74_1: C74.1 L7.1(1_Start) TP38.1 U2.25(OUT_1M)
NetC74_2: C74.2 TP40.1 U2.26(BST_1M)
NetC77_1: C77.1 L7.3(2_Start) R21.1
NetC78_1: C78.1 L7.2(1_Finish) R23.1
NetC81_1: C81.1 TP41.1 U2.38(BST_2P)
NetC81_2: C81.2 L8.4(2_Finish) TP42.1 U2.39(OUT_2P)
NetC82_1: C82.1 L8.1(1_Start) TP44.1 U2.34(OUT_2M)
NetC82_2: C82.2 TP46.1 U2.35(BST_2M)
NetC85_1: C85.1 L8.3(2_Start) R27.1
NetC86_1: C86.1 L8.2(1_Finish) R28.1
NetC89_1: C89.1 TP47.1 U2.46(BST_3P)
NetC89_2: C89.2 L9.4(2_Finish) TP48.1 U2.47(OUT_3P)
NetC90_1: C90.1 L9.1(1_Start) TP50.1 U2.42(OUT_3M)
NetC90_2: C90.2 TP52.1 U2.43(BST_3M)
NetC93_1: C93.1 L9.3(2_Start) R30.1
NetC94_1: C94.1 L9.2(1_Finish) R31.1
NetC97_1: C97.1 TP53.1 U2.55(BST_4P)
NetC97_2: C97.2 L10.4(2_Finish) TP54.1 U2.56(OUT_4P)
NetC98_1: C98.1 L10.1(1_Start) TP56.1 U2.50(OUT_4M)
NetC98_2: C98.2 TP58.1 U2.51(BST_4M)
NetC101_1: C101.1 L10.3(2_Start) R32.1
NetC102_1: C102.1 L10.2(1_Finish) R33.1
NetD8_1: D8.1(A) R173.2
NetD8_2: D8.2(K) U2.61(~{FAULT})
NetJ2_2: U2.5(SCLK) ; port SCLK
NetJ4_2: U2.6(FSYNC) ; port FSYNC
NetJ11_2: U2.13(SCL) ; port SCL
NetJ11_3: U2.12(SDA) ; port SDA
NetJ19_2: J20.2 U2.7(SDIN_1) ; port SDIN2
NetJ20_1: J20.1 R26.1 U2.9(GPIO_1) ; port GPIO2_1
NetR9_2: R25.1 U2.10(GPIO_2) ; port GPIO2_2
NetR11_1: R11.1 R22.1 ; port ~{STBY1_2}
NetR20_2: R20.2 R29.1 ; port PDN_2
NetR24_1: R24.1 U2.62(GPIO_3) ; port GPIO2_3
NetR34_1: R34.1 R35.2 U2.11(I2C_ADDR)
NetR143_2: U2.8(SDOUT_1) ; port SDOUT_2

Not connected (* = marked no-connect by the designer): U2 58(NC)

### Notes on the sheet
- N/A
- CONTROL
- (near C73) GPIO
- I2S
- I2C

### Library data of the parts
C53 C56 C57 C61 C64 = CMP-0007139-3: as C1 on sheet TIDA-020088_TAS6684_1
C54 C58 C62 C65 C67 C69 = CMP-0750040-1: as C2 on sheet TIDA-020088_TAS6684_1
C55 C59 C63 C66 C68 C70 = CMP-0064935-2: as C3 on sheet TIDA-020088_TAS6684_1
C60 = CMP-0083622-1: as C8 on sheet TIDA-020088_TAS6684_1
C71 C74 C81 C82 C89 C90 C97 C98 = CMP-0007145-4: as C19 on sheet TIDA-020088_TAS6684_1
C72 C73 = CMP-0009660-3: as C20 on sheet TIDA-020088_TAS6684_1
C75 C76 C83 C84 C91 C92 C99 C100 = CMP-0007145-4: as C23 on sheet TIDA-020088_TAS6684_1
C77 C78 C85 C86 C93 C94 C101 C102 = CMP-0009152-2: as C25 on sheet TIDA-020088_TAS6684_1
C79 C80 C87 C88 C95 C96 C103 C104 = CMP-0007082-4: as C27 on sheet TIDA-020088_TAS6684_1
D8 = CMP-0002829-3: as D7 on sheet TIDA-020088_TAS6684_1
J20 = CMP-0075405-2: as J22 on sheet TIDA-020088_TAS6684_1
L6 = CMP-0084877-1: as L1 on sheet TIDA-020088_TAS6684_1
L7-L10 = CMP-0093075-1: as L2 on sheet TIDA-020088_TAS6684_1
R11 R29 = CMP-0025697-4: as R60 on sheet TIDA-020088_TAS6684_1
R20 R22 R25 = CMP-0025958-3: as R1 on sheet TIDA-020088_TAS6684_1
R21 R23 R27 R28 R30-R33 = CMP-0015017-3: as R2 on sheet TIDA-020088_TAS6684_1
R24 = CMP-0026231-2: as R5 on sheet TIDA-020088_TAS6684_1
R26 = CMP-0025958-3: as R7 on sheet TIDA-020088_TAS6684_1
R34 = CMP-0026852-3: RES, 1.0 k, 5%, 0.063 W, AEC-Q200 Grade 0, 0402; Manufacturer: Vishay-Dale; Power_W: 63mW; TempCo: 200 ppm/C; Value_Code: 1k00; Value: 1.0k; EIA_Code: E24; Res_ohm: 1k; SizeX_mm: 1; SizeY_mm: 0.5; SizeZ_mm: 0.6; Value2: 0.063W; AEC Qualified: Y; VDC_V: 50V; AEC Category: Q200; AEC Grade: 0
R35 = CMP-0025697-4: as R9 on sheet TIDA-020088_TAS6684_1
R173 = CMP-0026414-2: as R171 on sheet TIDA-020088_TAS6684_1
TP30-TP58 = CMP-0003825-1: 1mm Test Point, SMT; Manufacturer: Any
U2 = CMP-0122557-1: as U1 on sheet TIDA-020088_TAS6684_1

## Sheet TIDA-020088_MCU-MSPM0G3519SPZR.SchDoc
size 431 x 279 mm; Date: Not shown in title block; ApprovedBy: Not shown in title block; CheckedBy: Not shown in title block; Author: Not shown in title block; CompanyName: Not shown in title block; Engineer: Not shown in title block; Organization: Not shown in title block; Address1: Not shown in title block; Address2: Not shown in title block; Address3: Not shown in title block; Address4: Not shown in title block; DocumentNumber: 2; Revision: Use project parameter SCH_Rev; SheetNumber: 6; SheetTotal: 8; PageSetup: Record=PageOptions¦CenterHorizontal=True¦CenterVertical=True¦PrintScale=1.00¦XCorrection=1.00¦YCorrection=1.00¦PrintKind=0¦BorderSize=5000000¦LeftOffset=0¦BottomOffset=0¦Orientation=2¦PaperLength=1000¦PaperWidth=1000¦Scale=100¦PaperSource=15¦PrintQuality=600¦MediaType=1¦DitherType=10¦PaperKind=Letter¦PrintScaleMode=1
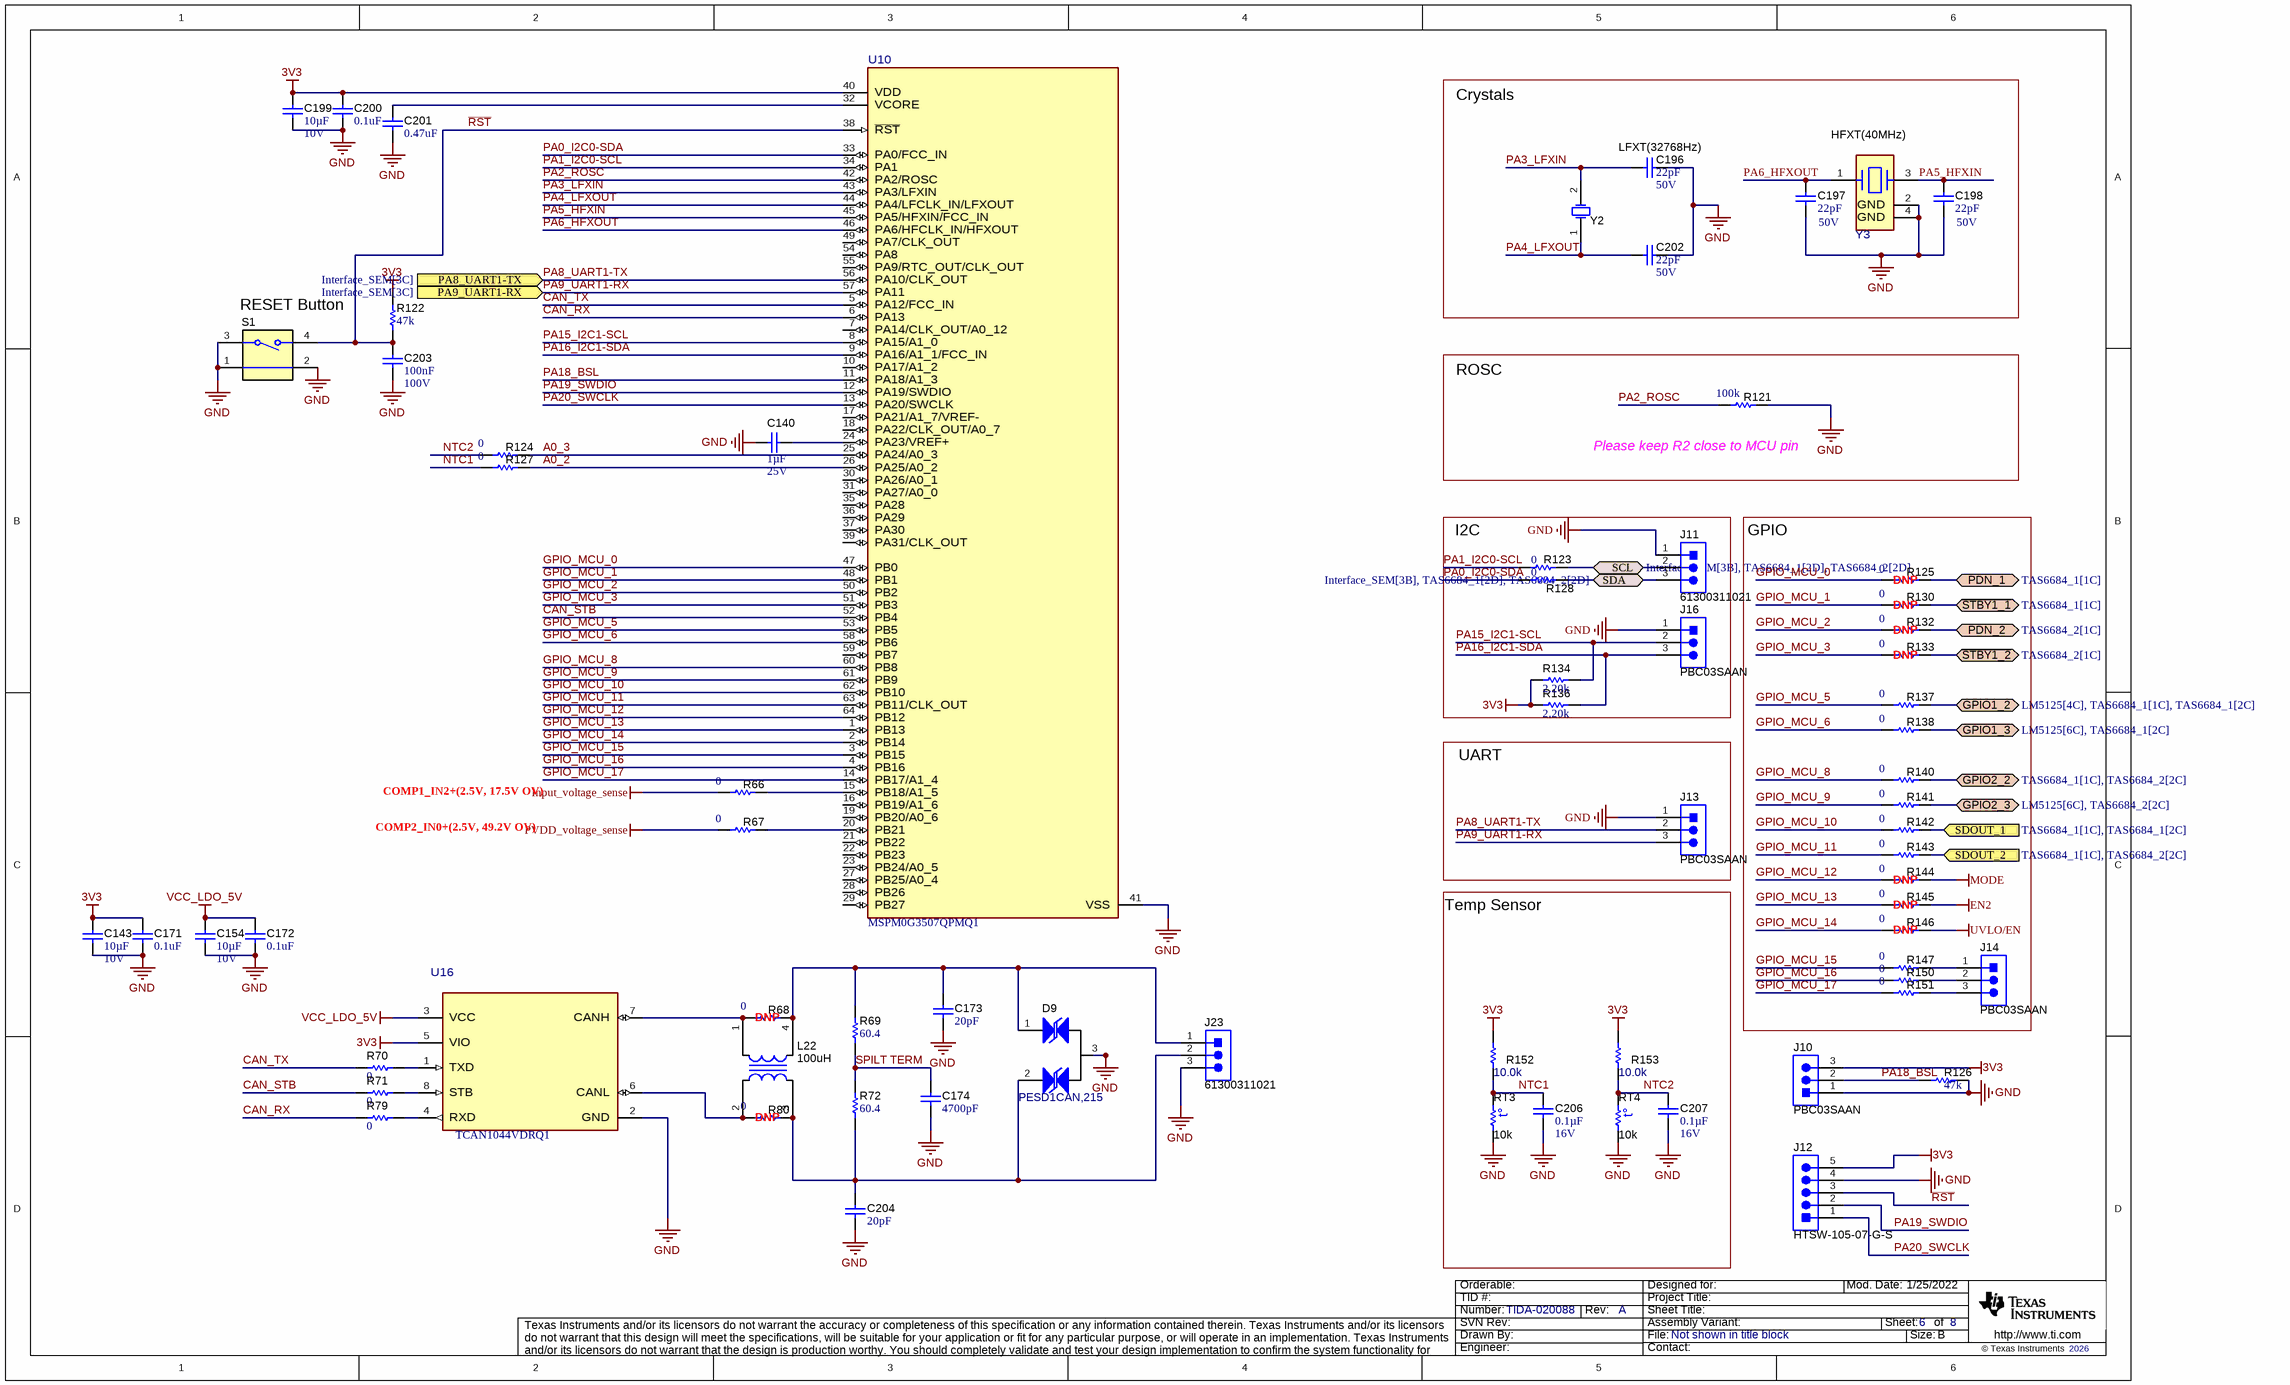
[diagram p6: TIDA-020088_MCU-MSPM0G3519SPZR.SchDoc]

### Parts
C140  Cap_F: 1µF  VDC_V: 25V  [0603]  (hidden comment: GCM188R71E105KA64D)
C143  Cap_F: 10µF  VDC_V: 10V  [0805_HV]  (hidden comment: C0805C106J8RACAUTO)
C154  Cap_F: 10µF  VDC_V: 10V  [0805_HV]  (hidden comment: C0805C106J8RACAUTO)
C171  ValueDisplayed: 0.1uF  [0402]  (hidden comment: GCM155R71H104KE02D)
C172  ValueDisplayed: 0.1uF  [0402]  (hidden comment: GCM155R71H104KE02D)
C173  ValueDisplayed: 20pF  [0402]  (hidden comment: GCQ1555C1H200JB01D)
C174  ValueDisplayed: 4700pF  [0603]  (hidden comment: GCM188R71H472KA37D)
C196  ValueDisplayed: 22pF  VDC_V: 50V  [0402]  (hidden comment: GCM1555C1H220JA16D)
C197  ValueDisplayed: 22pF  VDC_V: 50V  [0402]  (hidden comment: GCM1555C1H220JA16D)
C198  ValueDisplayed: 22pF  VDC_V: 50V  [0402]  (hidden comment: GCM1555C1H220JA16D)
C199  Cap_F: 10µF  VDC_V: 10V  [0805_HV]  (hidden comment: C0805C106J8RACAUTO)
C200  ValueDisplayed: 0.1uF  [0402]  (hidden comment: GCM155R71H104KE02D)
C201  ValueDisplayed: 0.47uF  [0603]  (hidden comment: GCM188R71E474KA64D)
C202  ValueDisplayed: 22pF  VDC_V: 50V  [0402]  (hidden comment: GCM1555C1H220JA16D)
C203  Cap_F: 100nF  VDC_V: 100V  [0603]  (hidden comment: GCJ188R72A104KA01D)
C204  ValueDisplayed: 20pF  [0402]  (hidden comment: GCQ1555C1H200JB01D)
C206  ValueDisplayed: 0.1µF  VDC_V: 16V  [0402]  (hidden comment: GCM155R71C104JA55D)
C207  ValueDisplayed: 0.1µF  VDC_V: 16V  [0402]  (hidden comment: GCM155R71C104JA55D)
D9  PESD1CAN,215  [SOT-23]
J10  PBC03SAAN  [PBC03SAAN]
J11  61300311021  [Wurth_61300311021]
J12  HTSW-105-07-G-S  [Samtec_HTSW-105-07-G-S]
J13  PBC03SAAN  [PBC03SAAN]
J14  PBC03SAAN  [PBC03SAAN]
J16  PBC03SAAN  [PBC03SAAN]
J23  61300311021  [Wurth_61300311021]
L22  ValueDisplayed: 100uH  [ACT45B]  (hidden comment: ACT45B-101-2P-TL003)
R66  ValueDisplayed: 0  [0603]  (hidden comment: CRCW06030000Z0EA)
R67  ValueDisplayed: 0  [0603]  (hidden comment: CRCW06030000Z0EA)
R68  DNP  ValueDisplayed: 0  [0603]  (no BOM)
R69  ValueDisplayed: 60.4  [1206]  (hidden comment: ERJ-8ENF60R4V)
R70  ValueDisplayed: 0  [0603]  (hidden comment: CRCW06030000Z0EA)
R71  ValueDisplayed: 0  [0603]  (hidden comment: CRCW06030000Z0EA)
R72  ValueDisplayed: 60.4  [1206]  (hidden comment: ERJ-8ENF60R4V)
R79  ValueDisplayed: 0  [0603]  (hidden comment: CRCW06030000Z0EA)
R80  DNP  ValueDisplayed: 0  [0603]  (no BOM)
R121  ValueDisplayed: 100k  [0402]  (hidden comment: CRCW0402100KFKED)
R122  ValueDisplayed: 47k  [0402]  (hidden comment: CRCW040247K0JNED)
R123  ValueDisplayed: 0  [0603]  (hidden comment: CRCW06030000Z0EA)
R124  ValueDisplayed: 0  [0603]  (hidden comment: CRCW06030000Z0EA)
R125  DNP  ValueDisplayed: 0  [0603]  (no BOM)
R126  ValueDisplayed: 47k  [0402]  (hidden comment: CRCW040247K0JNED)
R127  ValueDisplayed: 0  [0603]  (hidden comment: CRCW06030000Z0EA)
R128  ValueDisplayed: 0  [0603]  (hidden comment: CRCW06030000Z0EA)
R130  DNP  ValueDisplayed: 0  [0603]  (no BOM)
R132  DNP  ValueDisplayed: 0  [0603]  (no BOM)
R133  DNP  ValueDisplayed: 0  [0603]  (no BOM)
R134  ValueDisplayed: 2.20k  [0402]  (hidden comment: CRCW04022K20FKED)
R136  ValueDisplayed: 2.20k  [0402]  (hidden comment: CRCW04022K20FKED)
R137  ValueDisplayed: 0  [0603]  (hidden comment: CRCW06030000Z0EA)
R138  ValueDisplayed: 0  [0603]  (hidden comment: CRCW06030000Z0EA)
R140  ValueDisplayed: 0  [0603]  (hidden comment: CRCW06030000Z0EA)
R141  ValueDisplayed: 0  [0603]  (hidden comment: CRCW06030000Z0EA)
R142  ValueDisplayed: 0  [0603]  (hidden comment: CRCW06030000Z0EA)
R143  ValueDisplayed: 0  [0603]  (hidden comment: CRCW06030000Z0EA)
R144  DNP  ValueDisplayed: 0  [0603]  (no BOM)
R145  DNP  ValueDisplayed: 0  [0603]  (no BOM)
R146  DNP  ValueDisplayed: 0  [0603]  (no BOM)
R147  ValueDisplayed: 0  [0603]  (hidden comment: CRCW06030000Z0EA)
R150  ValueDisplayed: 0  [0603]  (hidden comment: CRCW06030000Z0EA)
R151  ValueDisplayed: 0  [0603]  (hidden comment: CRCW06030000Z0EA)
R152  ValueDisplayed: 10.0k  [0402L]  (hidden comment: CMP-0025958-3)
R153  ValueDisplayed: 10.0k  [0402L]  (hidden comment: CMP-0025958-3)
RT3  value 10k  [0603S]  (hidden comment: NCP18XH103D03RB)
RT4  value 10k  [0603S]  (hidden comment: NCP18XH103D03RB)
S1  1188E-1K2-V-TR  [SW_1188E]  (value not drawn)
U10  MSPM0G3507QPMQ1  [PM0064A-MFG]
U16  TCAN1044VDRQ1  [D0008A-MFG]
Y2  X1A0001410014  [Epson_FC-135]  (value not drawn)
Y3  X1E0000210179  [FP-X1E0000210179_TSX-3225-MFG]  (value not drawn)

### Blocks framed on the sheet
Crystals: C196-C198 C202 Y2 Y3
ROSC: R121
I2C: J11 J16 R123 R128 R134 R136
GPIO: J14 R125 R130 R132 R133 R137 R138 R140-R147 R150 R151
UART: J13
Temp Sensor: C206 C207 R152 R153 RT3 RT4

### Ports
GPIO1_2 (bidir, see LM5125[4C], TAS6684_1[1C], TAS6684_1[2C]), GPIO1_3 (bidir, see LM5125[6C], TAS6684_1[2C]), GPIO2_2 (bidir, see TAS6684_1[1C], TAS6684_2[2C]), GPIO2_3 (bidir, see LM5125[6C], TAS6684_2[2C]), PA8_UART1-TX (in, see Interface_SEM[3C]), PA9_UART1-RX (in, see Interface_SEM[3C]), PDN_1 (bidir, see TAS6684_1[1C]), PDN_2 (bidir, see TAS6684_2[1C]), SCL (bidir, see Interface_SEM[3B], TAS6684_1[2D], TAS6684_2[2D]), SDA (bidir, see Interface_SEM[3B], TAS6684_1[2D], TAS6684_2[2D]), SDOUT_1 (in, see TAS6684_1[1C], TAS6684_1[2C]), SDOUT_2 (in, see TAS6684_1[1C], TAS6684_2[2C]), ~{STBY1_1} (bidir, see TAS6684_1[1C]), ~{STBY1_2} (bidir, see TAS6684_2[1C])

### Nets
3V3: C143.2 C171.1 C199.2 C200.1 J10.3 J12.5 R122.2 R134.2 R136.2 R152.2 R153.2 U10.40(VDD) U16.5(VIO)
EN2: R145.2
GND: C140.1 C143.1 C154.1 C171.2 C172.2 C173.2 C174.2 C196.1 C197.1 C198.1 C199.1 C200.2 C201.2 C202.1 C203.2 C204.2 C206.1 C207.1 D9.3 J10.1 J11.1 J12.4 J13.1 J16.1 J23.3 R121.2 R126.1 RT3.1 RT4.1 S1.1 S1.2 S1.3 U10.41(VSS) U16.2(GND) Y3.2(GND) Y3.4(GND)
Input_voltage_sense: R66.1
MODE: R144.2
PVDD_voltage_sense: R67.1
UVLO/EN: R146.2
VCC_LDO_5V: C154.2 C172.1 U16.3(VCC)
A0_2: R127.2 U10.26(PA25/A0_2)
A0_3: R124.2 U10.25(PA24/A0_3)
CAN_RX: R79.2 U10.6(PA13)
CAN_STB: R71.2 U10.52(PB4)
CAN_TX: R70.2 U10.5(PA12/FCC_IN)
GPIO_MCU_0: R125.1 U10.47(PB0)
GPIO_MCU_1: R130.1 U10.48(PB1)
GPIO_MCU_2: R132.1 U10.50(PB2)
GPIO_MCU_3: R133.1 U10.51(PB3)
GPIO_MCU_5: R137.1 U10.53(PB5)
GPIO_MCU_6: R138.1 U10.58(PB6)
GPIO_MCU_8: R140.1 U10.60(PB8)
GPIO_MCU_9: R141.1 U10.61(PB9)
GPIO_MCU_10: R142.1 U10.62(PB10)
GPIO_MCU_11: R143.1 U10.63(PB11/CLK_OUT)
GPIO_MCU_12: R144.1 U10.64(PB12)
GPIO_MCU_13: R145.1 U10.1(PB13)
GPIO_MCU_14: R146.1 U10.2(PB14)
GPIO_MCU_15: R147.1 U10.3(PB15)
GPIO_MCU_16: R150.1 U10.4(PB16)
GPIO_MCU_17: R151.1 U10.14(PB17/A1_4)
NTC1: C206.2 R127.1 R152.1 RT3.2
NTC2: C207.2 R124.1 R153.1 RT4.2
PA0_I2C0-SDA: R128.1 U10.33(PA0/FCC_IN)
PA1_I2C0-SCL: R123.1 U10.34(PA1)
PA2_ROSC: R121.1 U10.42(PA2/ROSC)
PA3_LFXIN: C196.2 U10.43(PA3/LFXIN) Y2.2(OSC2)
PA4_LFXOUT: C202.2 U10.44(PA4/LFCLK_IN/LFXOUT) Y2.1(OSC1)
PA5_HFXIN: C198.2 U10.45(PA5/HFXIN/FCC_IN) Y3.3
PA6_HFXOUT: C197.2 U10.46(PA6/HFCLK_IN/HFXOUT) Y3.1
PA8_UART1-TX: J13.2 U10.56(PA10/CLK_OUT) ; port PA8_UART1-TX
PA9_UART1-RX: J13.3 U10.57(PA11) ; port PA9_UART1-RX
PA15_I2C1-SCL: J16.2 R134.1 U10.8(PA15/A1_0)
PA16_I2C1-SDA: J16.3 R136.1 U10.9(PA16/A1_1/FCC_IN)
PA18_BSL: J10.2 R126.2 U10.11(PA18/A1_3)
PA19_SWDIO: J12.2 U10.12(PA19/SWDIO)
PA20_SWCLK: J12.1 U10.13(PA20/SWCLK)
~{RST}: C203.1 J12.3 R122.1 S1.4 U10.38(~{RST})
SPILT TERM: C174.1 R69.1 R72.2
NetC140_2: C140.2 U10.24(PA23/VREF+)
NetC173_1: C173.1 D9.1 J23.1 L22.4 R68.2 R69.2
NetC201_1: C201.1 U10.32(VCORE)
NetC204_1: C204.1 D9.2 J23.2 L22.3 R72.1 R80.2
NetJ11_2: J11.2 R123.2 ; port SCL
NetJ11_3: J11.3 R128.2 ; port SDA
NetJ14_1: J14.1 R147.2
NetJ14_2: J14.2 R150.2
NetJ14_3: J14.3 R151.2
NetL22_1: L22.1 R68.1 U16.7(CANH)
NetL22_2: L22.2 R80.1 U16.6(CANL)
NetR1_2: R125.2 ; port PDN_1
NetR3_1: R130.2 ; port ~{STBY1_1}
NetR5_1: R138.2 ; port GPIO1_3
NetR6_1: R137.2 ; port GPIO1_2
NetR9_2: R140.2 ; port GPIO2_2
NetR11_1: R133.2 ; port ~{STBY1_2}
NetR20_2: R132.2 ; port PDN_2
NetR24_1: R141.2 ; port GPIO2_3
NetR66_2: R66.2 U10.15(PB18/A1_5)
NetR67_2: R67.2 U10.20(PB21)
NetR70_1: R70.1 U16.1(TXD)
NetR71_1: R71.1 U16.8(STB)
NetR79_1: R79.1 U16.4(RXD)
NetR142_2: R142.2 ; port SDOUT_1
NetR143_2: R143.2 ; port SDOUT_2

Not connected (* = marked no-connect by the designer): U10 7(PA14/CLK_OUT/A0_12) 10(PA17/A1_2) 16(PB19/A1_6) 17(PA21/A1_7/VREF-) 18(PA22/CLK_OUT/A0_7) 19(PB20/A0_6) 21(PB22) 22(PB23) 23(PB24/A0_5) 27(PB25/A0_4) 28(PB26) 29(PB27) 30(PA26/A0_1) 31(PA27/A0_0) 35(PA28) 36(PA29) 37(PA30) 39(PA31/CLK_OUT) 49(PA7/CLK_OUT) 54(PA8) 55(PA9/RTC_OUT/CLK_OUT) 59(PB7)

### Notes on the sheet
- (near C196) LFXT(32768Hz)
- HFXT(40MHz)
- (near S1) RESET Button
- (near R121) Please keep R2 close to MCU pin
- COMP2_IN0+(2.5V, 49.2V OV)
- COMP1_IN2+(2.5V, 17.5V OV)

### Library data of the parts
C140 = CMP-0007139-4: CAP, CERM, 1 uF, 25 V, +/- 10%, X7R, AEC-Q200 Grade 1, 0603; Manufacturer: MuRata; TaMin_C: -55°C; Polarized: N; SizeAreaWB_mm2: 4.68; Value1: Unknown; U/M: EA; Value: 1uF; TaMax_C: 125°C; SizeZ_mm: 1; SizeX_mm: 1.6; SizeY_mm: 0.8; SizeArea_mm2: 1.28; AEC Qualified: Y; AEC Category: Q200
C143 C154 C199 = CMP-0081061-1: CAP, CERM, 10 µF, 10 V,+/- 5%, X7R, AEC-Q200 Grade 1, 0805; Manufacturer: Kemet; SizeZ_mm: 1.45; AEC Qualified: Y; AEC Grade: 1; TaMin_C: -55°C; Polarized: N; SizeAreaWB_mm2: 6.75; U/M: EA; Value: 10uF; TaMax_C: 125°C; SizeX_mm: 2; SizeY_mm: 1.25; Cap_Case: 0805; SizeArea_mm2: 2.5; AEC Category: Q200
C171 C172 C200 = CMP-0006356-2: CAP, CERM, 0.1 uF, 50 V, +/- 10%, X7R, AEC-Q200 Grade 1, 0402; Manufacturer: MuRata; TaMin_C: -55°C; Polarized: N; SizeAreaWB_mm2: 3; Value1: Unknown; U/M: EA; Value: 0.1uF; TaMax_C: 125°C; SizeZ_mm: 0.6; SizeX_mm: 1; SizeY_mm: 0.5; Value2: 50V; AEC Qualified: Y; Cap_F: 100nF; AEC Category: Q200
C173 C204 = CMP-0085255-1: CAP, CERM, 20 pF, 50 V,+/- 5%, C0G/NP0, AEC-Q200 Grade 1, 0402; Manufacturer: MuRata; TaMin_C: -55°C; Polarized: N; SizeAreaWB_mm2: 3; U/M: EA; Value: 20pF; TaMax_C: 125°C; SizeZ_mm: 0.6; SizeX_mm: 1; SizeY_mm: 0.5; Value2: 50V; AEC Qualified: Y; AEC Category: Q200
C174 = CMP-0007146-4: CAP, CERM, 4700 pF, 50 V, +/- 10%, X7R, AEC-Q200 Grade 1, 0603; Manufacturer: MuRata; TaMin_C: -55°C; Polarized: N; SizeAreaWB_mm2: 4.68; Value1: Unknown; U/M: EA; Value: 4700pF; TaMax_C: 125°C; SizeZ_mm: 1; SizeX_mm: 1.6; SizeY_mm: 0.8; Value2: 50V; SizeArea_mm2: 1.28; AEC Qualified: Y; Cap_F: 4.7nF; AEC Category: Q200
C196-C198 C202 = CMP-0006348-2: CAP, CERM, 22 pF, 50 V, +/- 5%, C0G/NP0, AEC-Q200 Grade 1, 0402; Manufacturer: MuRata; TaMin_C: -55°C; Polarized: N; SizeAreaWB_mm2: 3; Value1: Unknown; U/M: EA; Value: 22pF; TaMax_C: 125°C; SizeZ_mm: 0.6; SizeX_mm: 1; SizeY_mm: 0.5; AEC Qualified: Y; AEC Category: Q200
C201 = CMP-0007142-4: CAP, CERM, 0.47 uF, 25 V, +/- 10%, X7R, AEC-Q200 Grade 1, 0603; Manufacturer: MuRata; TaMin_C: -55°C; Polarized: N; SizeAreaWB_mm2: 4.68; Value1: Unknown; U/M: EA; Value: 0.47uF; TaMax_C: 125°C; SizeZ_mm: 1; SizeX_mm: 1.6; SizeY_mm: 0.8; Value2: 25V; SizeArea_mm2: 1.28; AEC Qualified: Y; Cap_F: 470nF; AEC Category: Q200
C203 = CMP-0064935-2: as C3 on sheet TIDA-020088_TAS6684_1
C206 C207 = CMP-0080702-1: CAP, CERM, 0.1 µF, 16 V,+/- 5%, X7R, AEC-Q200 Grade 1, 0402; Manufacturer: MuRata; Polarized: N; Value: 0.1uF; U/M: EA; Cap_F: 100nF; TaMin_C: -55°C; TaMax_C: 125°C; SizeAreaWB_mm2: 3; SizeZ_mm: 0.6; SizeX_mm: 1; SizeY_mm: 0.5; AEC Qualified: Y; AEC Category: Q200
D9 = CMP-0005920-3: Diode, TVS, Bi, 24 V, 70 Vc, AEC-Q101, SOT-23; Manufacturer: NXP Semiconductor; Value: 24V; SizeArea_mm2: 7.5; AEC Category: Q101; Ppk: 200W; Ipp: 3A; Vbr_Min: 25.4V; SizeZ_mm: 1.1; AEC Qualified: Y; Vc: 70V; SizeX_mm: 2.5; SizeY_mm: 3; SizeAreaWB_mm2: 14; Vbr_Max: 30.3V
J10 J13 J14 J16 = CMP-0002334-1: Header, 100mil, 3x1, Gold, TH; Manufacturer: Sullins Connector Solutions; CNHeader: TRUE; Green_Lifecycle: Not Set; Green_REACh: Incomplete; CT: FALSE
J11 J23 = CMP-0054795-1: Header, 2.54 mm, 3x1, Gold, R/A, TH; Manufacturer: Wurth Elektronik; Pitch_mm: 2.54; Gender: Male; Shrouded: N; Row_Count: 1; CNHeader: TRUE; CT: FALSE
J12 = CMP-0075485-1: Header, 100mil, 5x1, Gold, TH; Manufacturer: Samtec; Green_REACh: Passed; CT: False; Green_Lifecycle: Active; CNHeader: True
L22 = CMP-0062430-2: Inductor, Ferrite, 100 uH, 0.15 A, 2 ohm, SMD; Manufacturer: TDK; Isat: 0.15A @ % inductance drop; Green_Lifecycle: Active; SizeAreaWB_mm2: 23.1; DCR_ohm: 2; Green_REACh: Passed; Value1: 2 ohm; Value: 100uH; Imax_A: 150mA; SizeZ_mm: 3; SizeX_mm: 4.5; SizeY_mm: 3.2; Value2: 0.15A; SizeArea_mm2: 14.4; Ind_H: 100µH; AEC Category: Q200
R66 R67 R123 R124 R127 R128 R137 R138 R140-R143 R147 R150 R151 = CMP-0025697-4: as R19 on sheet TIDA-020088_TAS6684_1
R68 R80 R125 R130 R132 R133 R144-R146 = CMP-0025697-4: as R9 on sheet TIDA-020088_TAS6684_1
R69 R72 = CMP-0017672-3: RES, 60.4, 1%, 0.25 W, AEC-Q200 Grade 0, 1206; Manufacturer: Panasonic; Power_W: 250mW; TempCo: 100 ppm/C; Value_Code: 60R4; Value: 60.4; EIA_Code: E96; SizeX_mm: 3.2; SizeY_mm: 1.6; SizeZ_mm: 1.35; Value2: 0.25W; SizeArea_mm2: 5.12; AEC Qualified: Y; VDC_V: 200V; AEC Category: Q200; AEC Grade: 0; SizeAreaWB_mm2: 10.92
R70 R71 R79 = CMP-0025697-4: as R60 on sheet TIDA-020088_TAS6684_1
R121 = CMP-0025950-3: RES, 100 k, 1%, 0.063 W, AEC-Q200 Grade 0, 0402; Manufacturer: Vishay-Dale; VDC_V: 50V; TempCo: 100 ppm/C; Power_W: 63mW; AEC Qualified: Y; SizeZ_mm: 0.6; AEC Grade: 0; Value: 100k; EIA_Code: E96; SizeX_mm: 1; SizeY_mm: 0.5; Value2: 0.063W; AEC Category: Q200
R122 R126 = CMP-0026935-3: RES, 47 k, 5%, 0.063 W, AEC-Q200 Grade 0, 0402; Manufacturer: Vishay-Dale; Power_W: 63mW; TempCo: 200 ppm/C; Value_Code: 47k0; Value: 47k; EIA_Code: E24; SizeX_mm: 1; SizeY_mm: 0.5; SizeZ_mm: 0.6; Value2: 0.063W; AEC Qualified: Y; VDC_V: 50V; AEC Category: Q200; AEC Grade: 0
R134 R136 = CMP-0026231-2: as R5 on sheet TIDA-020088_TAS6684_1
R152 R153 = CMP-0025958-3: RES, 10.0 k, 1%, 0.063 W, AEC-Q200 Grade 0, 0402; PartNumber: CRCW040210K0FKED; Manufacturer: Vishay-Dale; Value: 10.0k; Res_ohm: 10k; Value_Code: 10k0; Power_W: 63mW; Value2: 0.063W; VDC_V: 50V; TempCo: 100 ppm/C; EIA_Code: E96; SizeX_mm: 1; SizeY_mm: 0.5; SizeZ_mm: 0.6; AEC Qualified: Y; AEC Category: Q200; AEC Grade: 0
RT3 RT4 = CMP-0054545-2: Thermistor NTC, 10.0k ohm, 0.5%, 0603; Manufacturer: MuRata; TaMax_C: 125°C; SizeX_mm: 1.6; SizeY_mm: 0.8; TaMin_C: -40°C; Power_W: 100mW; SizeZ_mm: 1; SizeArea_mm2: 1.28; SizeAreaWB_mm2: 4.68; U/M: EA
S1 = CMP-0002328-1: Switch, SPST, 0.05 A, 12 VDC, SMD; Manufacturer: Diptronics; CurrentRating_mA: 50A; PositionCount: 1; SizeX_mm: 7.8; SizeY_mm: 3.5; SizeArea_mm2: 27.3; VDC_V: 12V; SizeAreaWB_mm2: 53.9
U10 = CMP-0120888-1: Automotive Mixed-Signal Microcontrollers With CAN-FD Interface; Manufacturer: Texas Instruments; SizeZ_mm: 1.6mm; AEC Qualified: Yes; AEC Grade: Grade 1; Core Architecture: ARM Cortex-M0+; Data Bus Width: 32bits; Frequency_Fixed: 80MHz; Interface: I2C,SPI,UART,CAN,LIN,IrDA,SMBus,Other; Max Supply Voltage: 3.6V; Memory Size: 128KBytes; Memory Type: FLASH; Min Supply Voltage: 1.62V; Number Of A/D Converters: 2; Number Of Adc Channels: 17; Number Of Cores: 1; Number Of I/Os: 60; Number Of Pwm Channels: 22; Number Of Timers/Counters: 7; Number Of Uart Channels: 4; Ram Size: 32KBytes; Standoff Height: 0.05mm; TaMax_C: +125°C; TaMin_C: -40°C; TJmax_C: +130°C
U16 = CMP-0032674-1: CAN Interface IC Automotive high speed CAN transceiver 8-SOIC -40 to 125; Manufacturer: Texas Instruments; SizeZ_mm: 1.75mm; AEC Qualified: No; Max Supply Voltage: 5.5V; Min Supply Voltage: 4.5V; Nominal Supply Current: 4.5-49mA; Standoff Height: 0.11mm; TaMax_C: +125°C; TaMin_C: -40°C; TJmax_C: +150°C
Y2 = CMP-0004693-3: Crystal, 32.768 KHz, 12.5 pF, SMD; Manufacturer: Epson; TaMax_C: 85°C; TaMin_C: -40°C
Y3 = CMP-0098168-2: Crystal 40MHz ±10ppm (Tol) ±20ppm (Stability) 12pF FUND 40Ohm 4-Pin Mini-CSMD T/R; Manufacturer: Seiko Epson; SizeZ_mm: 0.6mm; AEC Qualified: No; Esr: 40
